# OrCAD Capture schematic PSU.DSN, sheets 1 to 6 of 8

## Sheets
1 Hirose70239: size A; title: Adapter for connecting IR-256x192(FPC-39)  to IR-640x512(Hirose-70); rev: A1
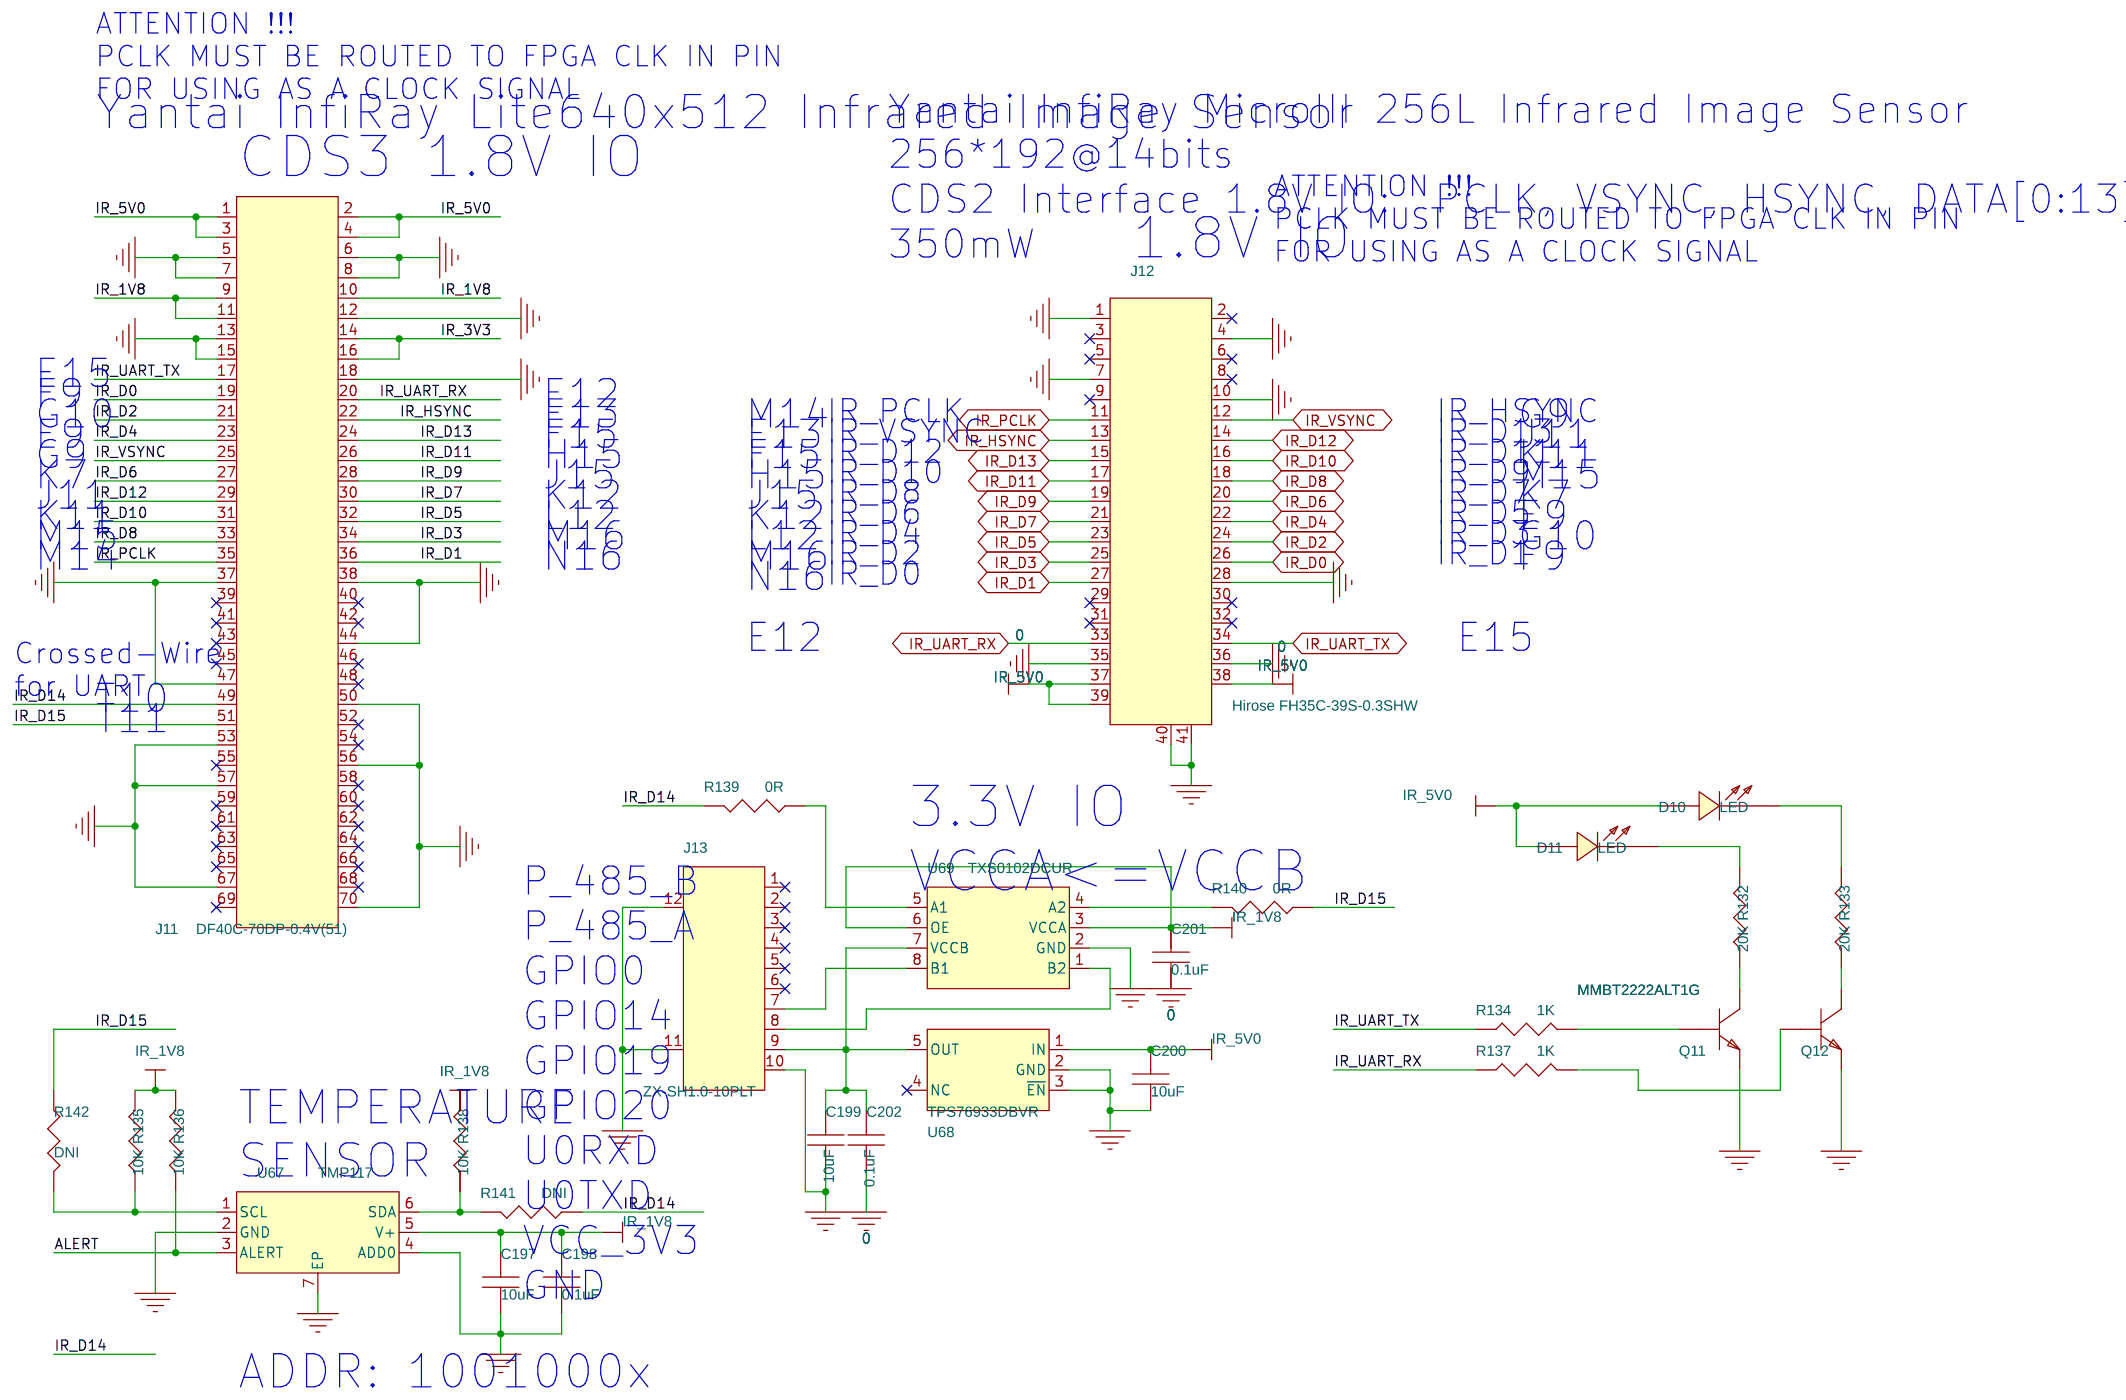
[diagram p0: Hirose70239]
2 ElectricFieldSensor: size A2
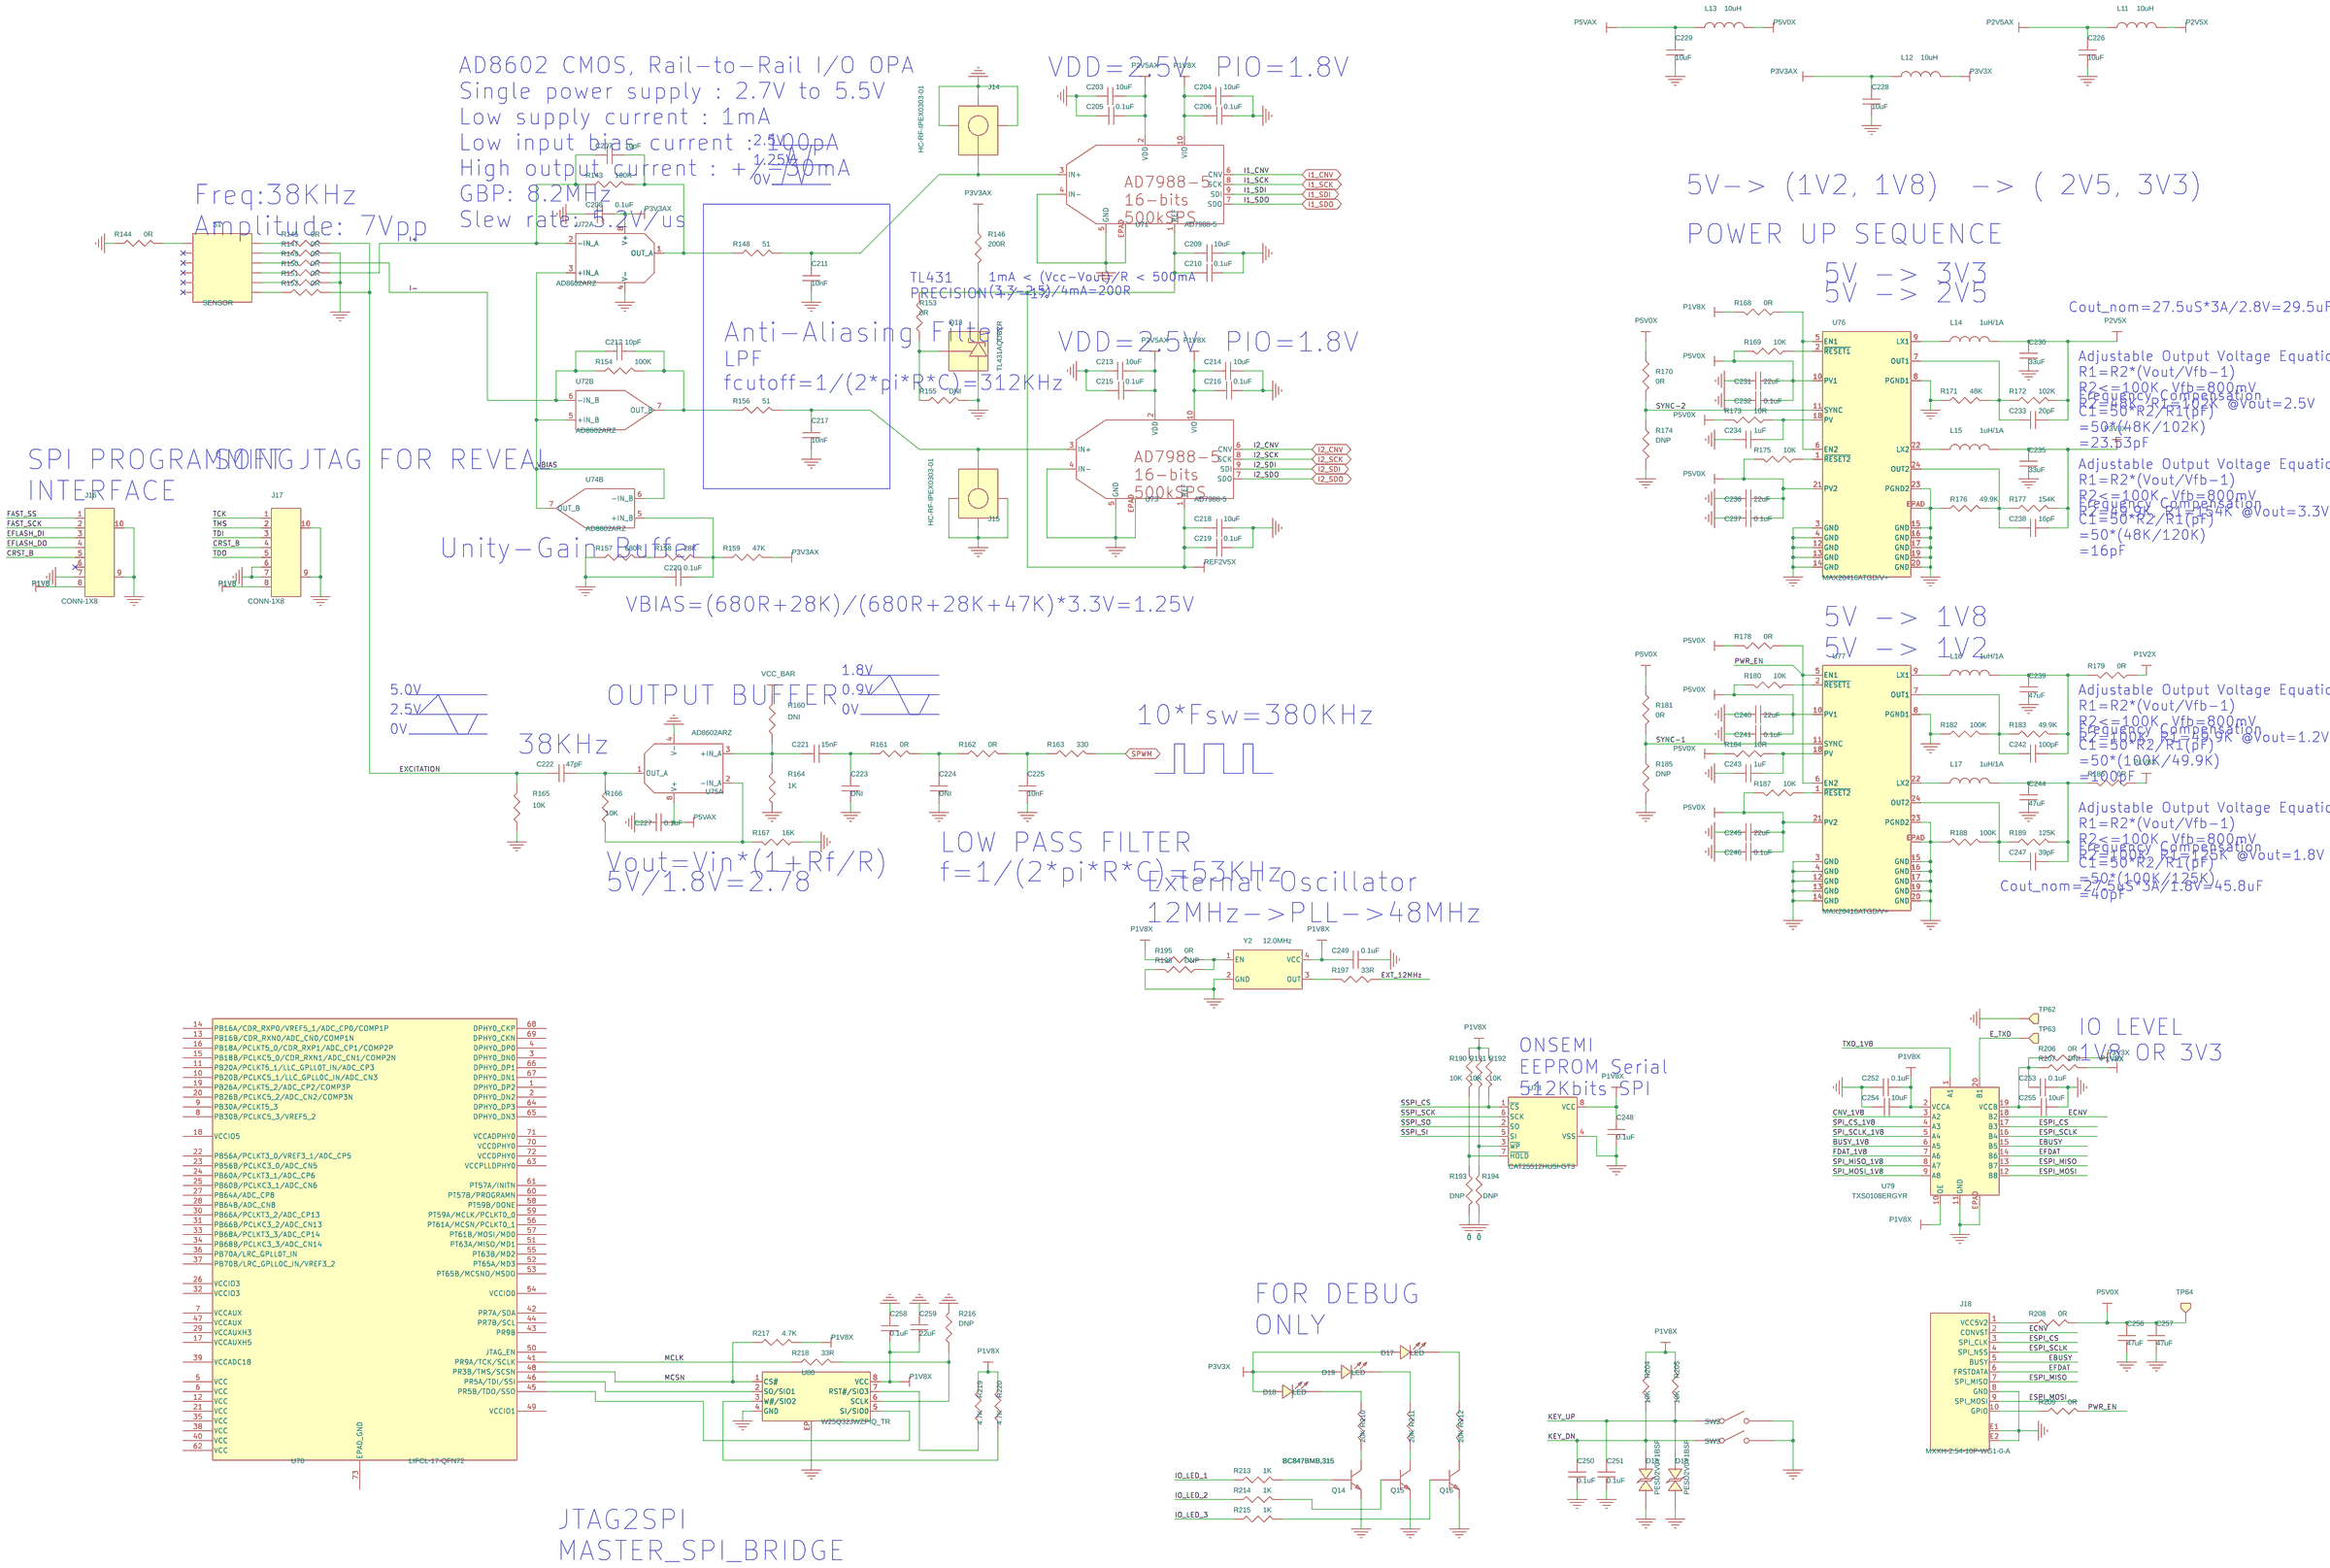
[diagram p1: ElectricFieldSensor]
3 PG_Adapter: size A; title: GENERIC PROGRAMMING ADAPTER FOR LATTICE FPGA
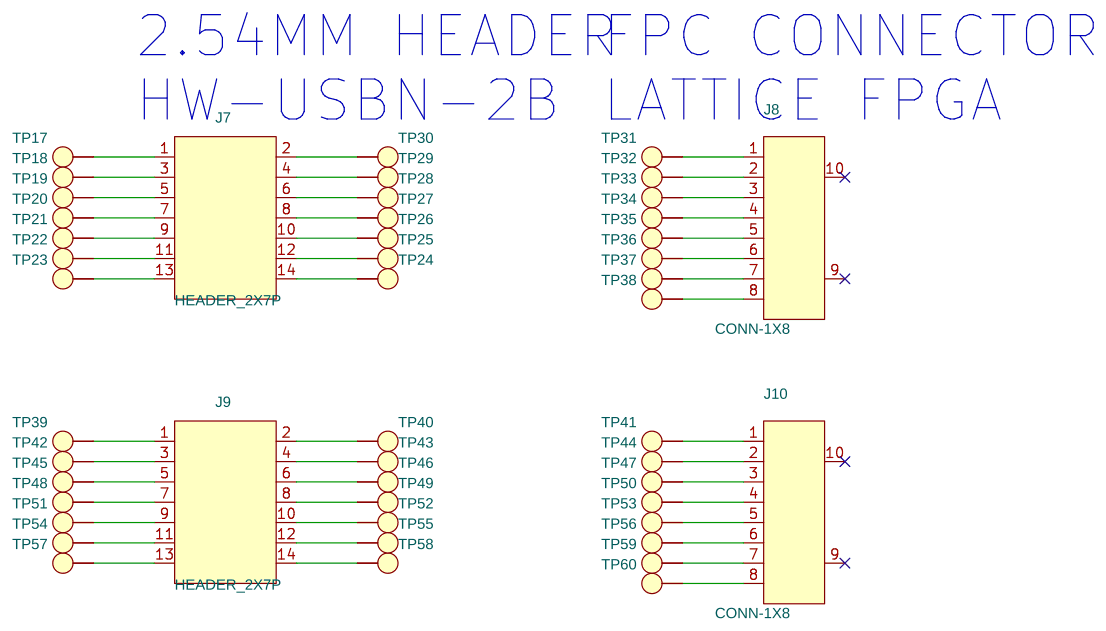
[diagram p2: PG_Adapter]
4 PSU1W: size A3
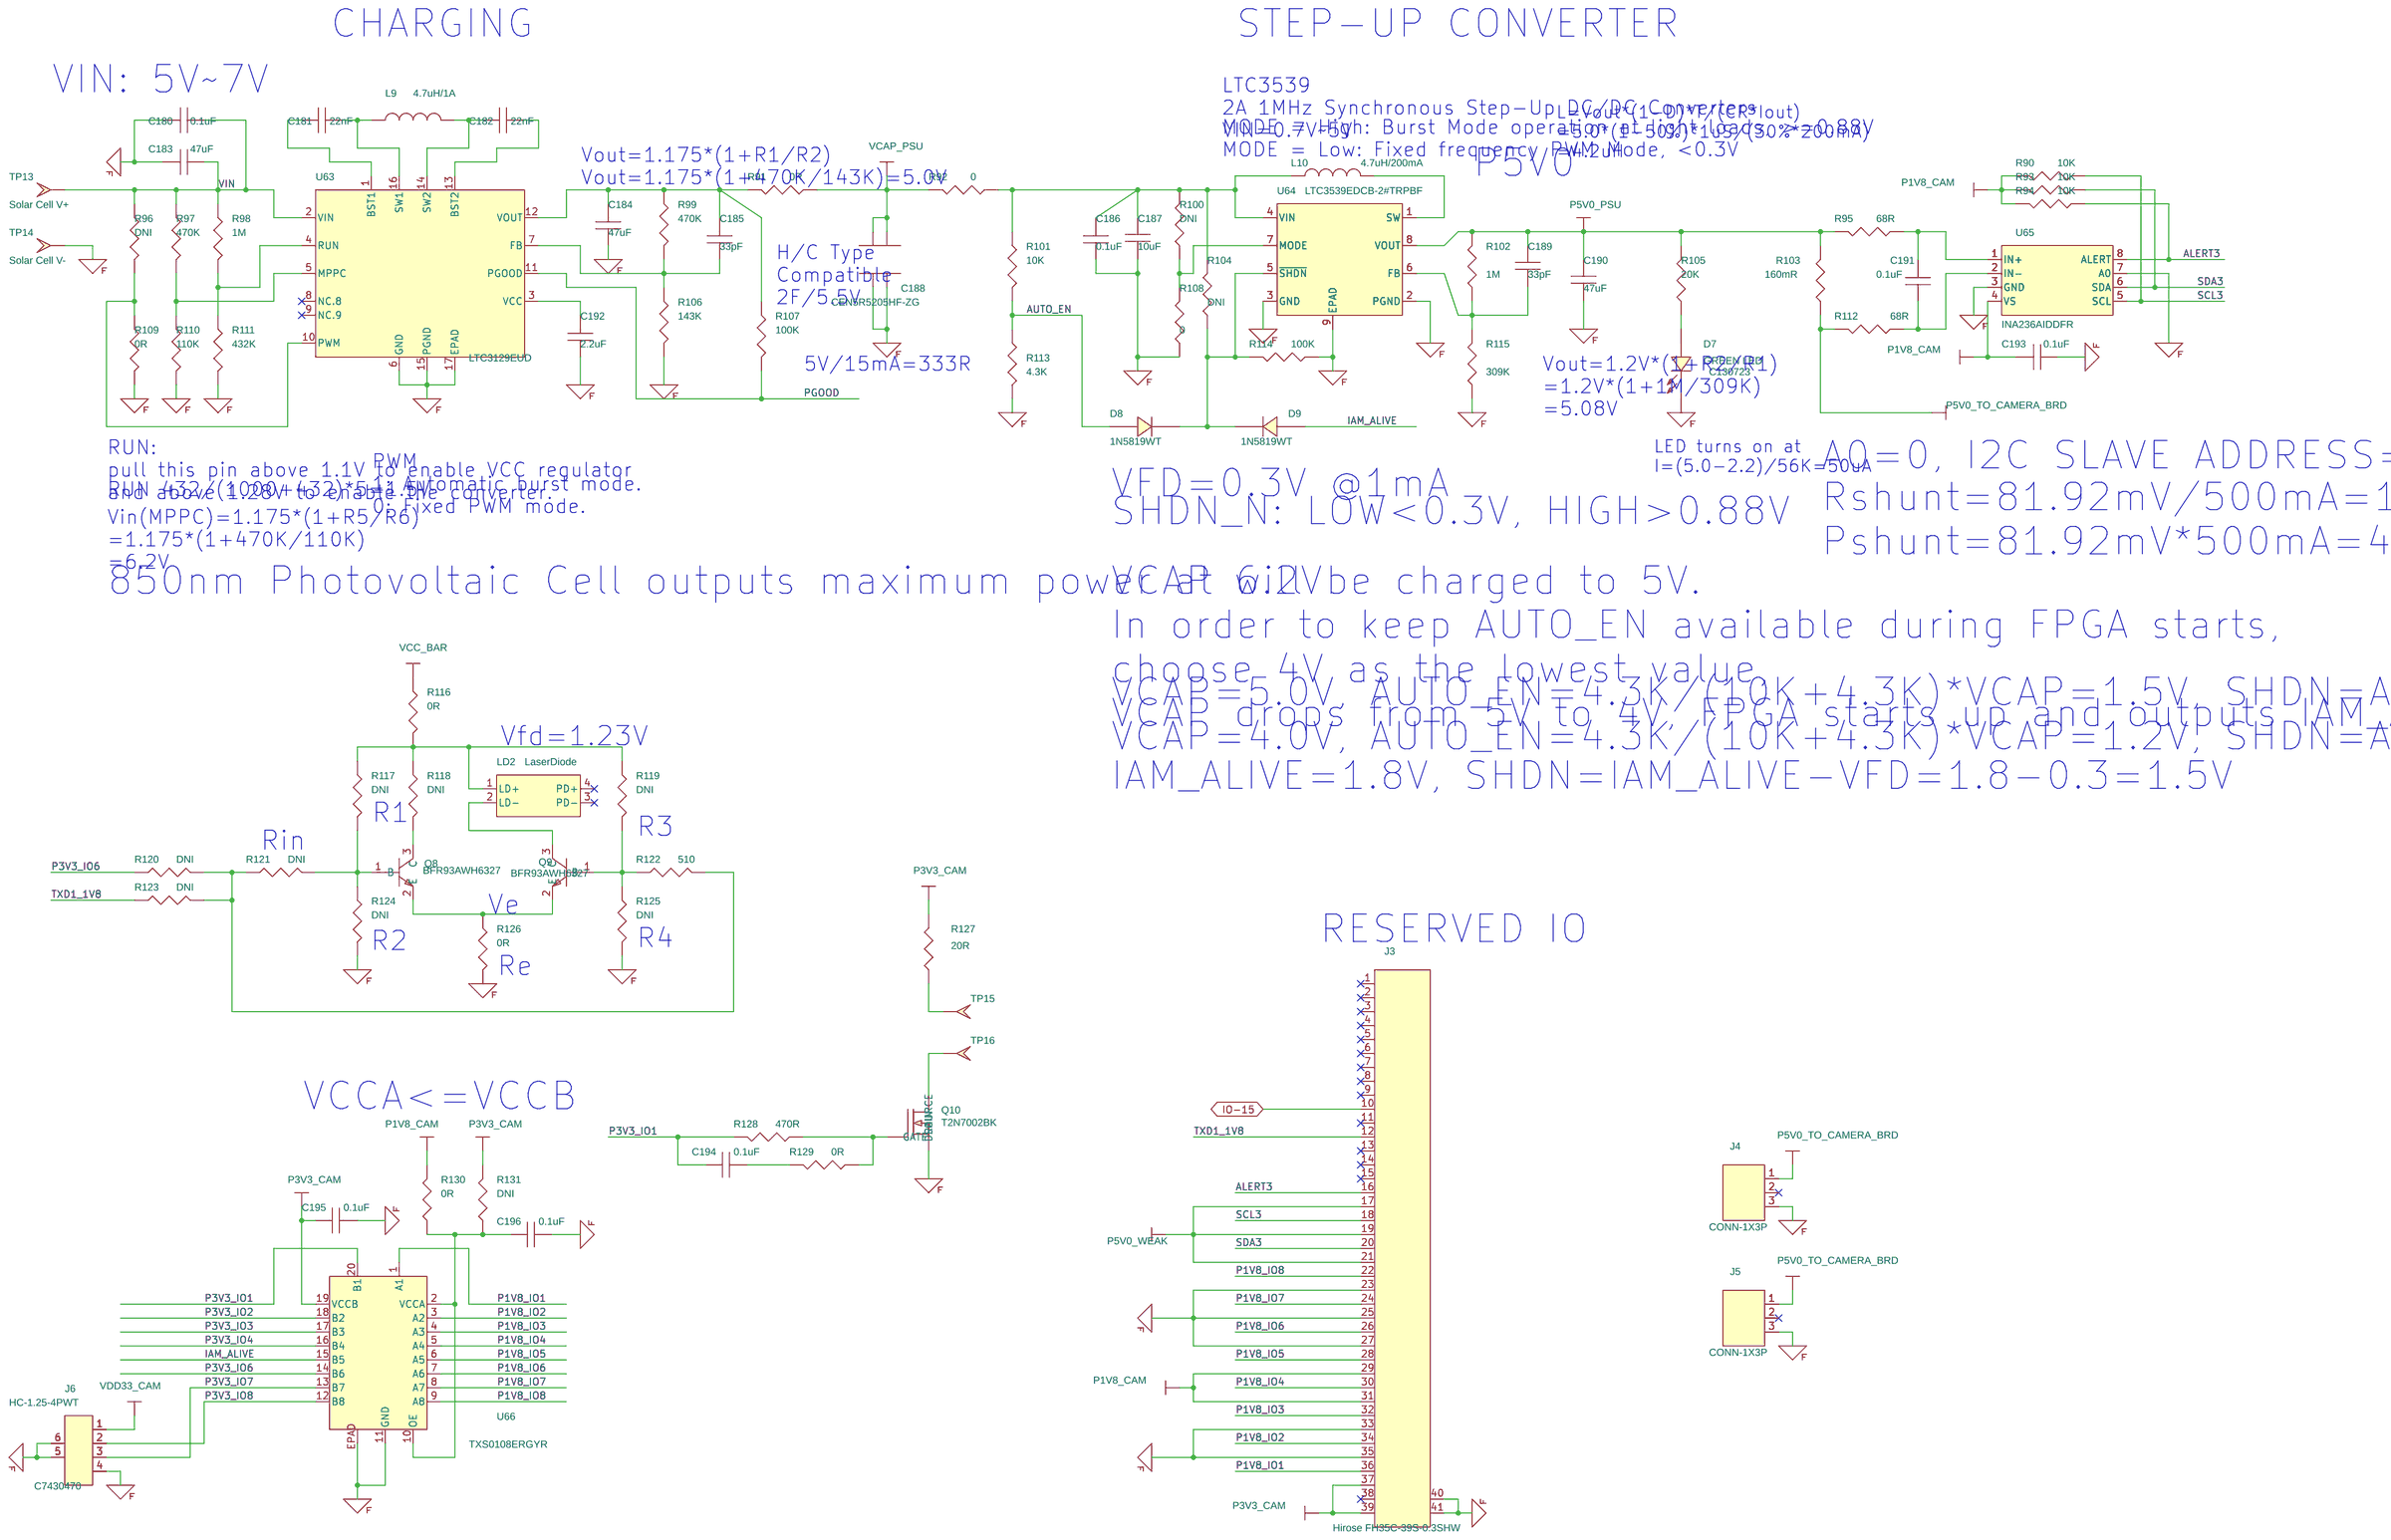
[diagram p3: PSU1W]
5 MAGIC2956: size A4; title: TMR SENSOR (CHINA DOMESTIC IC SUPPLIER); note: TMR PROJECT
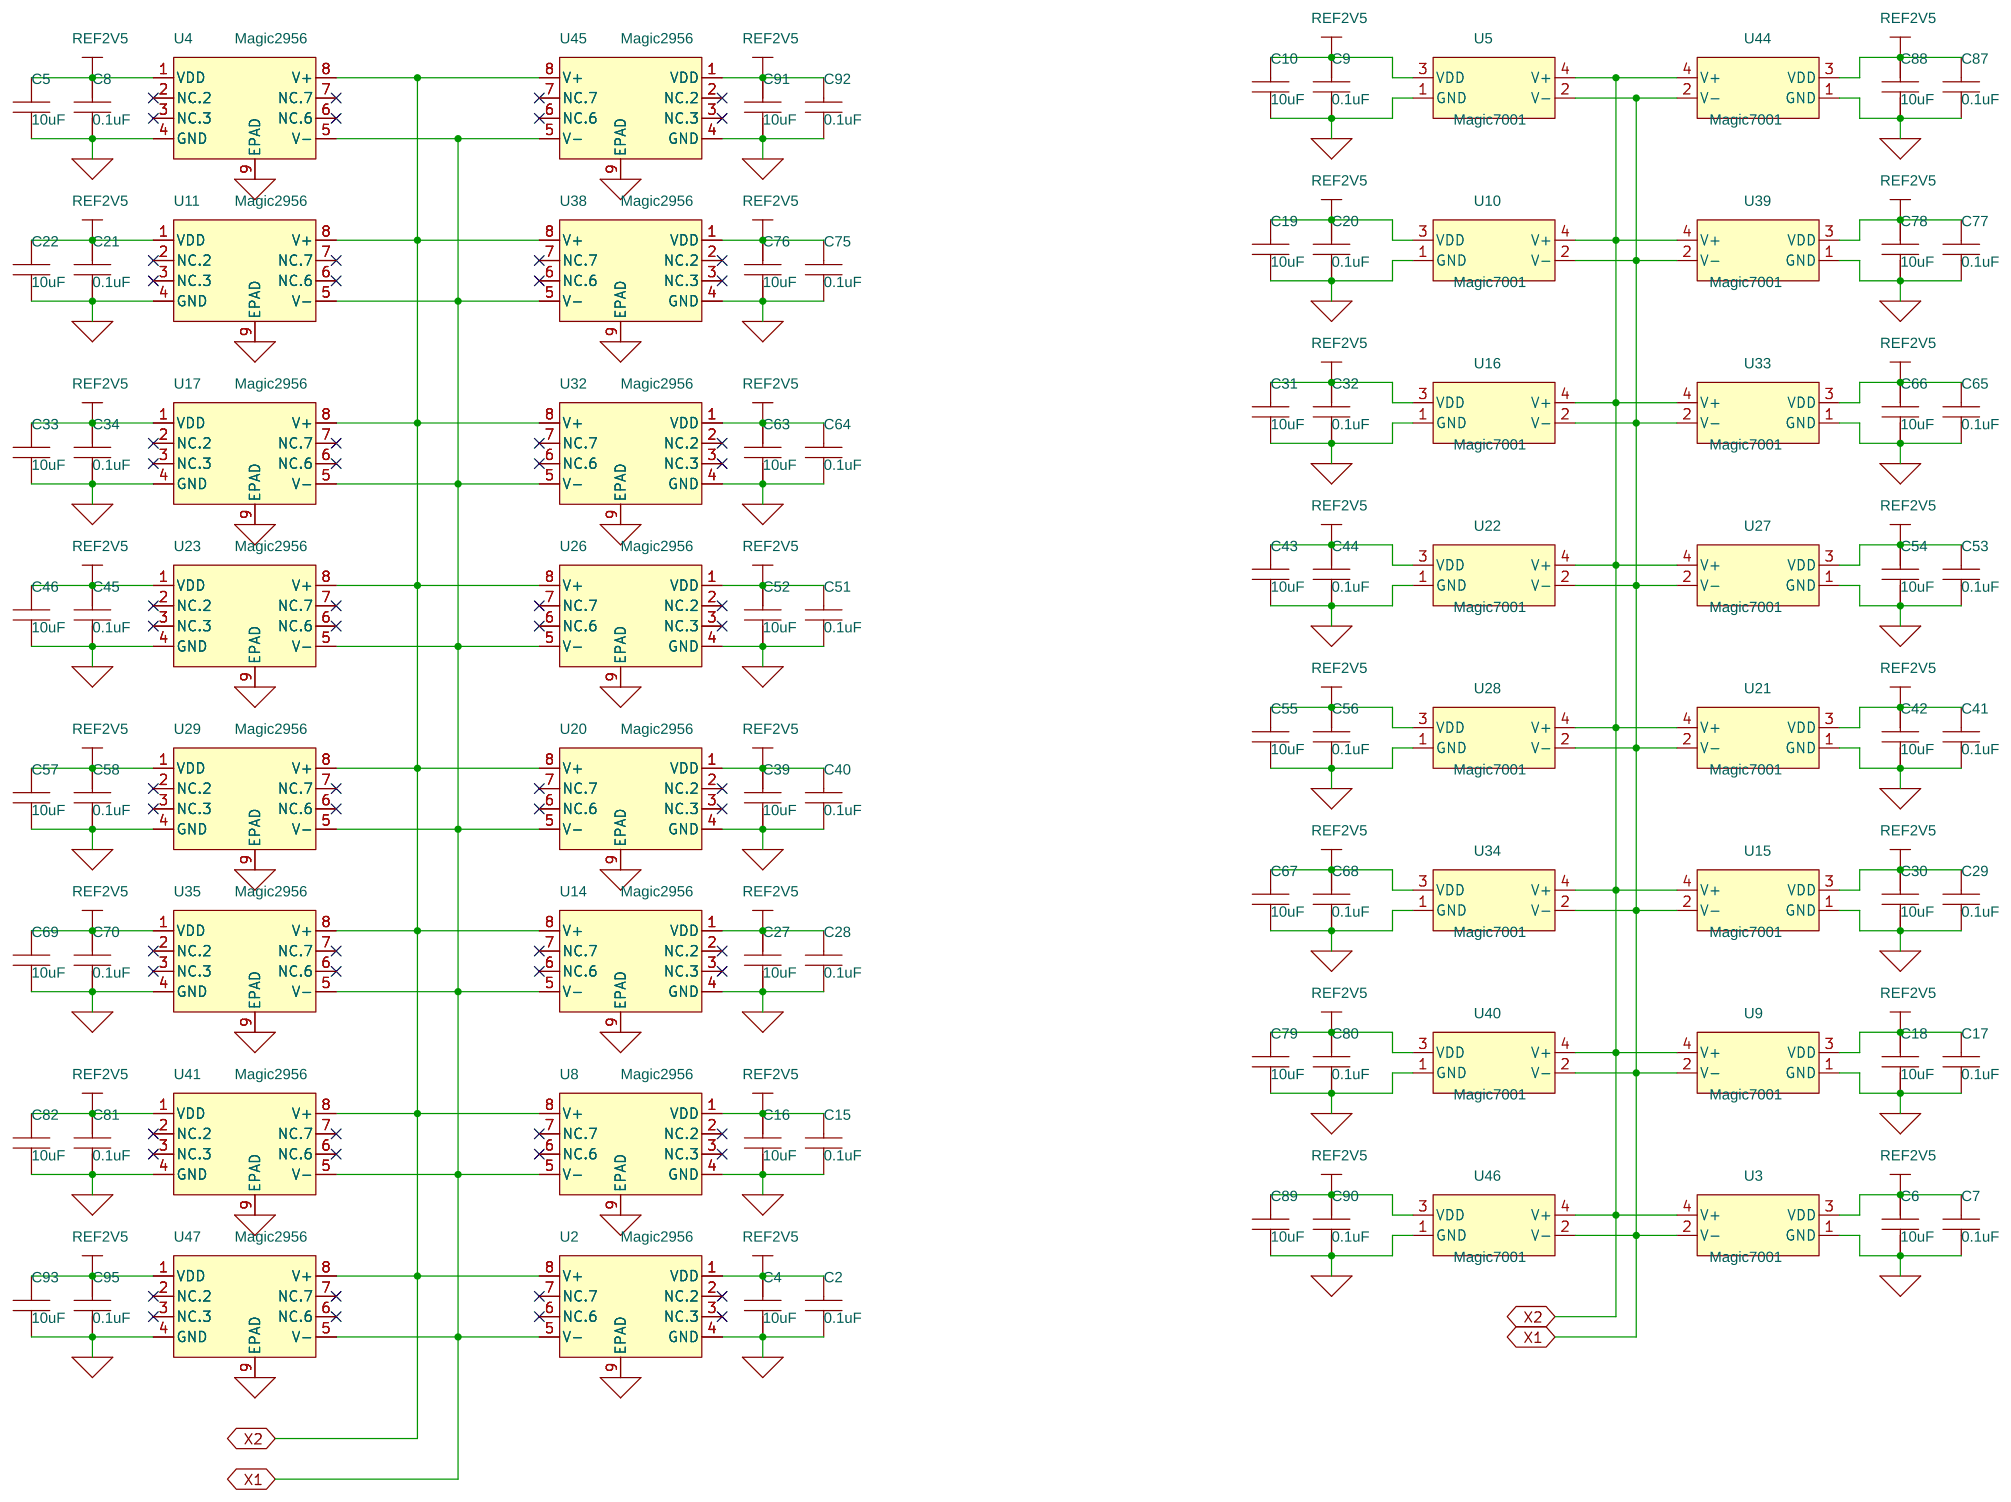
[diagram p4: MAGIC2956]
6 ADC: size A; title: TMR SENSOR ( FOREIGN IC SUPPLIER); note: TMR PROJECT
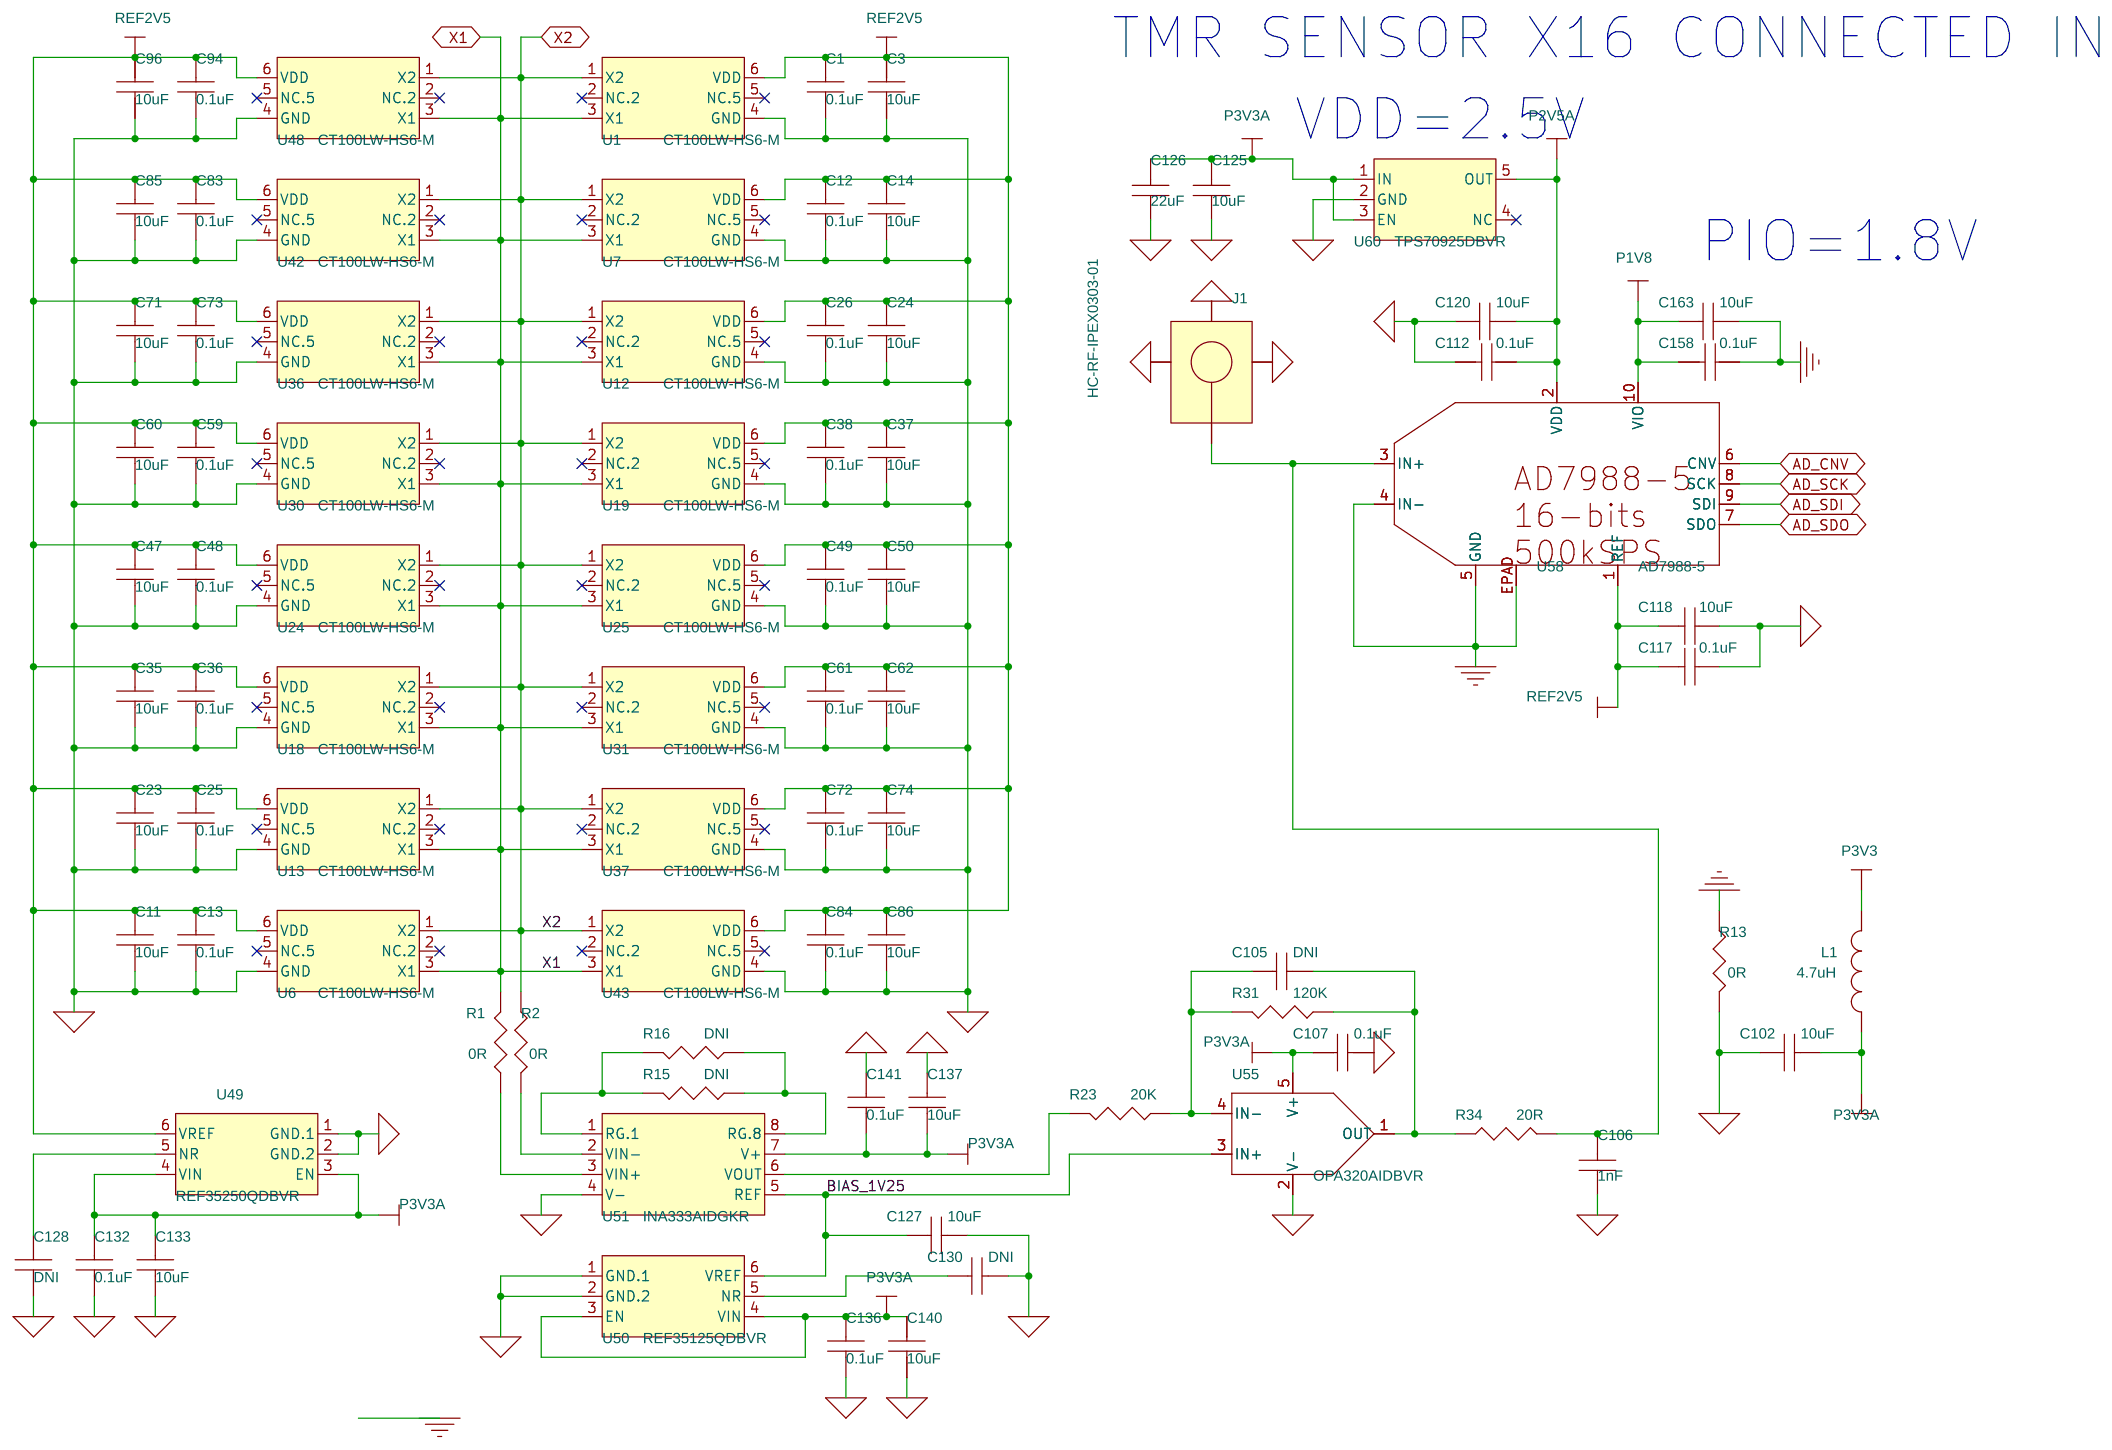
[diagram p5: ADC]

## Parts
sheet ADC
C1  0.1uF  [C0402_SMT]
C3  10uF  [C0402_SMT]
C11  10uF  [C0402_SMT]
C12  0.1uF  [C0402_SMT]
C13  0.1uF  [C0402_SMT]
C14  10uF  [C0402_SMT]
C23  10uF  [C0402_SMT]
C24  10uF  [C0402_SMT]
C25  0.1uF  [C0402_SMT]
C26  0.1uF  [C0402_SMT]
C35  10uF  [C0402_SMT]
C36  0.1uF  [C0402_SMT]
C37  10uF  [C0402_SMT]
C38  0.1uF  [C0402_SMT]
C47  10uF  [C0402_SMT]
C48  0.1uF  [C0402_SMT]
C49  0.1uF  [C0402_SMT]
C50  10uF  [C0402_SMT]
C59  0.1uF  [C0402_SMT]
C60  10uF  [C0402_SMT]
C61  0.1uF  [C0402_SMT]
C62  10uF  [C0402_SMT]
C71  10uF  [C0402_SMT]
C72  0.1uF  [C0402_SMT]
C73  0.1uF  [C0402_SMT]
C74  10uF  [C0402_SMT]
C83  0.1uF  [C0402_SMT]
C84  0.1uF  [C0402_SMT]
C85  10uF  [C0402_SMT]
C86  10uF  [C0402_SMT]
C94  0.1uF  [C0402_SMT]
C96  10uF  [C0402_SMT]
C102  10uF  [C0402_SMT]
C105  DNI  [C0402_SMT]
C106  1nF  [C0402_SMT]
C107  0.1uF  [C0402_SMT]
C112  0.1uF  [C0402_SMT]
C117  0.1uF  [C0402_SMT]
C118  10uF  [C0402_SMT]
C120  10uF  [C0402_SMT]
C125  10uF  [C0402_SMT]
C126  22uF  [C0603_SMT]
C127  10uF  [C0402_SMT]
C128  DNI  [C0402_SMT]
C130  DNI  [C0402_SMT]
C132  0.1uF  [C0402_SMT]
C133  10uF  [C0402_SMT]
C136  0.1uF  [C0402_SMT]
C137  10uF  [C0402_SMT]
C140  10uF  [C0402_SMT]
C141  0.1uF  [C0402_SMT]
C158  0.1uF  [C0402_SMT]
C163  10uF  [C0402_SMT]
J1  HC-RF-IPEX0303-01  [IPEX_SMD_4P]
L1  4.7uH  [L0603_SMT]
R1  0R  [R0402_SMT]
R2  0R  [R0402_SMT]
R13  0R  [R0402_SMT]
R15  DNI  [R0402_SMT]
R16  DNI  [R0402_SMT]
R23  20K  [R0402_SMT]
R31  120K  [R0402_SMT]
R34  20R  [R0402_SMT]
U1  CT100LW-HS6-M  [TSOT-23-6]
U6  CT100LW-HS6-M  [TSOT-23-6]
U7  CT100LW-HS6-M  [TSOT-23-6]
U12  CT100LW-HS6-M  [TSOT-23-6]
U13  CT100LW-HS6-M  [TSOT-23-6]
U18  CT100LW-HS6-M  [TSOT-23-6]
U19  CT100LW-HS6-M  [TSOT-23-6]
U24  CT100LW-HS6-M  [TSOT-23-6]
U25  CT100LW-HS6-M  [TSOT-23-6]
U30  CT100LW-HS6-M  [TSOT-23-6]
U31  CT100LW-HS6-M  [TSOT-23-6]
U36  CT100LW-HS6-M  [TSOT-23-6]
U37  CT100LW-HS6-M  [TSOT-23-6]
U42  CT100LW-HS6-M  [TSOT-23-6]
U43  CT100LW-HS6-M  [TSOT-23-6]
U48  CT100LW-HS6-M  [TSOT-23-6]
U49  REF35250QDBVR  [SOT-23-6]
U50  REF35125QDBVR  [SOT-23-6]
U51  INA333AIDGKR  [MSOP-8]
U55  OPA320AIDBVR  [SOT-23-5]
U58  AD7988-5  [MSOP-10]
U60  TPS70925DBVR  [SOT-23-5]
sheet ElectricFieldSensor
C203  10uF  [C0402_SMT]
C204  10uF  [C0402_SMT]
C205  0.1uF  [C0402_SMT]
C206  0.1uF  [C0402_SMT]
C207  10pF  [C0402_SMT]
C208  0.1uF  [C0402_SMT]
C209  10uF  [C0402_SMT]
C210  0.1uF  [C0402_SMT]
C211  10nF  [C0402_SMT]
C212  10pF  [C0402_SMT]
C213  10uF  [C0402_SMT]
C214  10uF  [C0402_SMT]
C215  0.1uF  [C0402_SMT]
C216  0.1uF  [C0402_SMT]
C217  10nF  [C0402_SMT]
C218  10uF  [C0402_SMT]
C219  0.1uF  [C0402_SMT]
C220  0.1uF  [C0402_SMT]
C221  15nF  [C0402_SMT]
C222  47pF  [C0402_SMT]
C223  DNI  [C0402_SMT]
C224  DNI  [C0402_SMT]
C225  10nF  [C0402_SMT]
C226  10uF  [C0603_SMT]
C227  0.1uF  [C0402_SMT]
C228  10uF  [C0603_SMT]
C229  10uF  [C0603_SMT]
C230  33uF  [C1206_SMT]
C231  22uF  [C0603_SMT]
C232  0.1uF  [C0402_SMT]
C233  20pF  [C0402_SMT]
C234  1uF  [C0402_SMT]
C235  33uF  [C1206_SMT]
C236  22uF  [C0603_SMT]
C237  0.1uF  [C0402_SMT]
C238  16pF  [C0402_SMT]
C239  47uF  [C1206_SMT]
C240  22uF  [C0603_SMT]
C241  0.1uF  [C0402_SMT]
C242  100pF  [C0402_SMT]
C243  1uF  [C0402_SMT]
C244  47uF  [C1206_SMT]
C245  22uF  [C0603_SMT]
C246  0.1uF  [C0402_SMT]
C247  39pF  [C0402_SMT]
C248  0.1uF  [C0402_SMT]
C249  0.1uF  [C0402_SMT]
C250  0.1uF  [C0402_SMT]
C251  0.1uF  [C0402_SMT]
C252  0.1uF  [C0402_SMT]
C253  0.1uF  [C0402_SMT]
C254  10uF  [C0402_SMT]
C255  10uF  [C0402_SMT]
C256  47uF  [C0603_SMT]
C257  47uF  [C0603_SMT]
C258  0.1uF  [C0201_SMT]
C259  22uF  [C0603_SMT]
D15  PESD2V0Y1BSF  [DSN0603-2]
D16  PESD2V0Y1BSF  [DSN0603-2]
D17  LED  [LED0402_SMT]
D18  LED  [LED0402_SMT]
D19  LED  [LED0402_SMT]
J14  HC-RF-IPEX0303-01  [IPEX_SMD_4P]
J15  HC-RF-IPEX0303-01  [IPEX_SMD_4P]
J16  CONN-1X8  [FPC-0D5-8P]
J17  CONN-1X8  [FPC-0D5-8P]
J18  MXXH-2.54-10P-WG1-0-A  [CONN_SMD_1X10P_2D5]
L11  10uH  [L0603_SMT]
L12  10uH  [L0603_SMT]
L13  10uH  [L0603_SMT]
L14  1uH/1A  [IND_SMD_4D4X4D2]
L15  1uH/1A  [IND_SMD_4D4X4D2]
L16  1uH/1A  [IND_SMD_4D4X4D2]
L17  1uH/1A  [IND_SMD_4D4X4D2]
Q13  TL431AQDBZR  [SOT-23-3]
Q14  BC847BMB,315  [DFN-3-1X0D6]
Q15  BC847BMB,315  [DFN-3-1X0D6]
Q16  BC847BMB,315  [DFN-3-1X0D6]
R143  100K  [R0402_SMT]
R144  0R  [R0402_SMT]
R145  0R  [R0402_SMT]
R146  200R  [R0402_SMT]
R147  0R  [R0402_SMT]
R148  51  [R0402_SMT]
R149  0R  [R0402_SMT]
R150  0R  [R0402_SMT]
R151  0R  [R0402_SMT]
R152  0R  [R0402_SMT]
R153  0R  [R0402_SMT]
R154  100K  [R0402_SMT]
R155  DNI  [R0402_SMT]
R156  51  [R0402_SMT]
R157  680R  [R0402_SMT]
R158  28K  [R0402_SMT]
R159  47K  [R0402_SMT]
R160  DNI  [R0402_SMT]
R161  0R  [R0402_SMT]
R162  0R  [R0402_SMT]
R163  330  [R0402_SMT]
R164  1K  [R0402_SMT]
R165  10K  [R0402_SMT]
R166  10K  [R0402_SMT]
R167  16K  [R0402_SMT]
R168  0R  [R0402_SMT]
R169  10K  [R0402_SMT]
R170  0R  [R0402_SMT]
R171  48K  [R0402_SMT]
R172  102K  [R0402_SMT]
R173  10R  [R0402_SMT]
R174  DNP  [R0402_SMT]
R175  10K  [R0402_SMT]
R176  49.9K  [R0402_SMT]
R177  154K  [R0402_SMT]
R178  0R  [R0402_SMT]
R179  0R  [R0402_SMT]
R180  10K  [R0402_SMT]
R181  0R  [R0402_SMT]
R182  100K  [R0402_SMT]
R183  49.9K  [R0402_SMT]
R184  10R  [R0402_SMT]
R185  DNP  [R0402_SMT]
R186  0R  [R0402_SMT]
R187  10K  [R0402_SMT]
R188  100K  [R0402_SMT]
R189  125K  [R0402_SMT]
R190  10K  [R0402_SMT]
R191  10K  [R0402_SMT]
R192  10K  [R0402_SMT]
R193  DNP  [R0402_SMT]
R194  DNP  [R0402_SMT]
R195  0R  [R0402_SMT]
R196  DNP  [R0402_SMT]
R197  33R  [R0402_SMT]
R204  10K  [R0402_SMT]
R205  10K  [R0402_SMT]
R206  0R  [R0402_SMT]
R207  DNI  [R0402_SMT]
R208  0R  [R0603_SMT]
R209  0R  [R0402_SMT]
R210  20K  [R0201_SMT]
R211  20K  [R0201_SMT]
R212  20K  [R0201_SMT]
R213  1K  [R0201_SMT]
R214  1K  [R0201_SMT]
R215  1K  [R0201_SMT]
R216  DNP  [R0201_SMT]
R217  4.7K  [R0201_SMT]
R218  33R  [R0201_SMT]
R219  4.7K  [R0201_SMT]
R220  4.7K  [R0201_SMT]
S1  SENSOR  [EFS-12X10-12P]
SW2  SW KEY-SPST  [SW_SMD_2P_L3D9_W3D0_P4D5]
SW3  SW KEY-SPST  [SW_SMD_2P_L3D9_W3D0_P4D5]
TP62  T POINT F  [TP_THR_CIR_1D0_1D5]
TP63  T POINT F  [TP_THR_CIR_1D0_1D5]
TP64  T POINT F  [TP_THR_CIR_1D0_1D5]
U70  LIFCL-17-QFN72  [QFN-72-EP]
U71  AD7988-5  [MSOP-10]
U72  AD8602ARZ  [SOIC-8]  (sections A,B)
U73  AD7988-5  [MSOP-10]
U74  AD8602ARZ  [SOIC-8]  (section B)
U75  AD8602ARZ  [SOIC-8]  (section A)
U76  MAX20416ATGD/V+  [TQFN-24]
U77  MAX20416ATGD/V+  [TQFN-24]
U78  CAT25512HU5I-GT3  [UDFN-8-2x3]
U79  TXS0108ERGYR  [VQFN-20]
U80  W25Q32JWZPIQ_TR  [WSON-8-EP-6X5MM]
Y2  12.0MHz  [SMD2520-4P]
sheet Hirose70239
C197  10uF  [C0402_SMT]
C198  0.1uF  [C0402_SMT]
C199  10uF  [C0402_SMT]
C200  10uF  [C0402_SMT]
C201  0.1uF  [C0402_SMT]
C202  0.1uF  [C0402_SMT]
D10  LED  [LED0402_SMT]
D11  LED  [LED0402_SMT]
J11  DF40C-70DP-0.4V(51)  [DF40C-70DP-0D4V-51]
J12  Hirose FH35C-39S-0.3SHW  [FH35C-39S-0D3SHW]
J13  ZX-SH1.0-10PLT  [CONN_1X10P_SH1D0]
Q11  MMBT2222ALT1G  [SOT-23-3]
Q12  MMBT2222ALT1G  [SOT-23-3]
R132  20K  [R0402_SMT]
R133  20K  [R0402_SMT]
R134  1K  [R0402_SMT]
R135  10K  [R0402_SMT]
R136  10K  [R0402_SMT]
R137  1K  [R0402_SMT]
R138  10K  [R0402_SMT]
R139  0R  [R0402_SMT]
R140  0R  [R0402_SMT]
R141  DNI  [R0402_SMT]
R142  DNI  [R0402_SMT]
U67  TMP117  [WDFN-6-EP-2x2]
U68  TPS76933DBVR  [SOT-23-5]
U69  TXS0102DCUR  [VSSOP-8]
sheet MAGIC2956
C2  0.1uF  [C0402_SMT]
C4  10uF  [C0402_SMT]
C5  10uF  [C0402_SMT]
C6  10uF  [C0402_SMT]
C7  0.1uF  [C0402_SMT]
C8  0.1uF  [C0402_SMT]
C9  0.1uF  [C0402_SMT]
C10  10uF  [C0402_SMT]
C15  0.1uF  [C0402_SMT]
C16  10uF  [C0402_SMT]
C17  0.1uF  [C0402_SMT]
C18  10uF  [C0402_SMT]
C19  10uF  [C0402_SMT]
C20  0.1uF  [C0402_SMT]
C21  0.1uF  [C0402_SMT]
C22  10uF  [C0402_SMT]
C27  10uF  [C0402_SMT]
C28  0.1uF  [C0402_SMT]
C29  0.1uF  [C0402_SMT]
C30  10uF  [C0402_SMT]
C31  10uF  [C0402_SMT]
C32  0.1uF  [C0402_SMT]
C33  10uF  [C0402_SMT]
C34  0.1uF  [C0402_SMT]
C39  10uF  [C0402_SMT]
C40  0.1uF  [C0402_SMT]
C41  0.1uF  [C0402_SMT]
C42  10uF  [C0402_SMT]
C43  10uF  [C0402_SMT]
C44  0.1uF  [C0402_SMT]
C45  0.1uF  [C0402_SMT]
C46  10uF  [C0402_SMT]
C51  0.1uF  [C0402_SMT]
C52  10uF  [C0402_SMT]
C53  0.1uF  [C0402_SMT]
C54  10uF  [C0402_SMT]
C55  10uF  [C0402_SMT]
C56  0.1uF  [C0402_SMT]
C57  10uF  [C0402_SMT]
C58  0.1uF  [C0402_SMT]
C63  10uF  [C0402_SMT]
C64  0.1uF  [C0402_SMT]
C65  0.1uF  [C0402_SMT]
C66  10uF  [C0402_SMT]
C67  10uF  [C0402_SMT]
C68  0.1uF  [C0402_SMT]
C69  10uF  [C0402_SMT]
C70  0.1uF  [C0402_SMT]
C75  0.1uF  [C0402_SMT]
C76  10uF  [C0402_SMT]
C77  0.1uF  [C0402_SMT]
C78  10uF  [C0402_SMT]
C79  10uF  [C0402_SMT]
C80  0.1uF  [C0402_SMT]
C81  0.1uF  [C0402_SMT]
C82  10uF  [C0402_SMT]
C87  0.1uF  [C0402_SMT]
C88  10uF  [C0402_SMT]
C89  10uF  [C0402_SMT]
C90  0.1uF  [C0402_SMT]
C91  10uF  [C0402_SMT]
C92  0.1uF  [C0402_SMT]
C93  10uF  [C0402_SMT]
C95  0.1uF  [C0402_SMT]
U2  Magic2956  [DFN8L]
U3  Magic7001  [SSIP4L]
U4  Magic2956  [DFN8L]
U5  Magic7001  [SSIP4L]
U8  Magic2956  [DFN8L]
U9  Magic7001  [SSIP4L]
U10  Magic7001  [SSIP4L]
U11  Magic2956  [DFN8L]
U14  Magic2956  [DFN8L]
U15  Magic7001  [SSIP4L]
U16  Magic7001  [SSIP4L]
U17  Magic2956  [DFN8L]
U20  Magic2956  [DFN8L]
U21  Magic7001  [SSIP4L]
U22  Magic7001  [SSIP4L]
U23  Magic2956  [DFN8L]
U26  Magic2956  [DFN8L]
U27  Magic7001  [SSIP4L]
U28  Magic7001  [SSIP4L]
U29  Magic2956  [DFN8L]
U32  Magic2956  [DFN8L]
U33  Magic7001  [SSIP4L]
U34  Magic7001  [SSIP4L]
U35  Magic2956  [DFN8L]
U38  Magic2956  [DFN8L]
U39  Magic7001  [SSIP4L]
U40  Magic7001  [SSIP4L]
U41  Magic2956  [DFN8L]
U44  Magic7001  [SSIP4L]
U45  Magic2956  [DFN8L]
U46  Magic7001  [SSIP4L]
U47  Magic2956  [DFN8L]
sheet PG_Adapter
J7  HEADER_2X7P  [HEADER_2X7P_2D54]
J8  CONN-1X8  [FPC-0D5-8P]
J9  HEADER_2X7P  [HEADER_2X7P_2D54]
J10  CONN-1X8  [FPC-0D5-8P]
TP17  T POINT R  [TP_THR_CIR_2D0_1D2]
TP18  T POINT R  [TP_THR_CIR_2D0_1D2]
TP19  T POINT R  [TP_THR_CIR_2D0_1D2]
TP20  T POINT R  [TP_THR_CIR_2D0_1D2]
TP21  T POINT R  [TP_THR_CIR_2D0_1D2]
TP22  T POINT R  [TP_THR_CIR_2D0_1D2]
TP23  T POINT R  [TP_THR_CIR_2D0_1D2]
TP24  T POINT R  [TP_THR_CIR_2D0_1D2]
TP25  T POINT R  [TP_THR_CIR_2D0_1D2]
TP26  T POINT R  [TP_THR_CIR_2D0_1D2]
TP27  T POINT R  [TP_THR_CIR_2D0_1D2]
TP28  T POINT R  [TP_THR_CIR_2D0_1D2]
TP29  T POINT R  [TP_THR_CIR_2D0_1D2]
TP30  T POINT R  [TP_THR_CIR_2D0_1D2]
TP31  T POINT R  [TP_THR_CIR_2D0_1D2]
TP32  T POINT R  [TP_THR_CIR_2D0_1D2]
TP33  T POINT R  [TP_THR_CIR_2D0_1D2]
TP34  T POINT R  [TP_THR_CIR_2D0_1D2]
TP35  T POINT R  [TP_THR_CIR_2D0_1D2]
TP36  T POINT R  [TP_THR_CIR_2D0_1D2]
TP37  T POINT R  [TP_THR_CIR_2D0_1D2]
TP38  T POINT R  [TP_THR_CIR_2D0_1D2]
TP39  T POINT R  [TP_THR_CIR_2D0_1D2]
TP40  T POINT R  [TP_THR_CIR_2D0_1D2]
TP41  T POINT R  [TP_THR_CIR_2D0_1D2]
TP42  T POINT R  [TP_THR_CIR_2D0_1D2]
TP43  T POINT R  [TP_THR_CIR_2D0_1D2]
TP44  T POINT R  [TP_THR_CIR_2D0_1D2]
TP45  T POINT R  [TP_THR_CIR_2D0_1D2]
TP46  T POINT R  [TP_THR_CIR_2D0_1D2]
TP47  T POINT R  [TP_THR_CIR_2D0_1D2]
TP48  T POINT R  [TP_THR_CIR_2D0_1D2]
TP49  T POINT R  [TP_THR_CIR_2D0_1D2]
TP50  T POINT R  [TP_THR_CIR_2D0_1D2]
TP51  T POINT R  [TP_THR_CIR_2D0_1D2]
TP52  T POINT R  [TP_THR_CIR_2D0_1D2]
TP53  T POINT R  [TP_THR_CIR_2D0_1D2]
TP54  T POINT R  [TP_THR_CIR_2D0_1D2]
TP55  T POINT R  [TP_THR_CIR_2D0_1D2]
TP56  T POINT R  [TP_THR_CIR_2D0_1D2]
TP57  T POINT R  [TP_THR_CIR_2D0_1D2]
TP58  T POINT R  [TP_THR_CIR_2D0_1D2]
TP59  T POINT R  [TP_THR_CIR_2D0_1D2]
TP60  T POINT R  [TP_THR_CIR_2D0_1D2]
sheet PSU1W
C180  0.1uF  [C0402_SMT]
C181  22nF  [C0402_SMT]
C182  22nF  [C0402_SMT]
C183  47uF  [C1206_SMT]
C184  47uF  [C1206_SMT]
C185  33pF  [C0402_SMT]
C186  0.1uF  [C0402_SMT]
C187  10uF  [C0603_SMT]
C188  CEN5R5205HF-ZG  [SUC_C_5D0_21D5_H_20D5]
C189  33pF  [C0402_SMT]
C190  47uF  [C1206]
C191  0.1uF  [C0402_SMT]
C192  2.2uF  [C0402_SMT]
C193  0.1uF  [C0402_SMT]
C194  0.1uF  [C0402_SMT]
C195  0.1uF  [C0402_SMT]
C196  0.1uF  [C0402_SMT]
D7  GREEN LED  [LED0402_SMT]
D8  1N5819WT  [SOD-523]
D9  1N5819WT  [SOD-523]
J3  Hirose FH35C-39S-0.3SHW  [FH35C-39S-0D3SHW_REV]
J4  CONN-1X3P  [CONN-1x3P-2D54]
J5  CONN-1X3P  [CONN-1x3P-2D54]
J6  HC-1.25-4PWT  [SMD-1D25-4P-DEG0]
L9  4.7uH/1A  [IND_SMD_4D4X4D2]
L10  4.7uH/200mA  [IND_SMD_4D4X4D2]
LD2  LaserDiode  [LD_CIR_THR_4P]
Q8  BFR93AWH6327  [SOT23-3]
Q9  BFR93AWH6327  [SOT23-3]
Q10  T2N7002BK  [SOT23-3]
R90  10K  [R0402_SMT]
R91  0R  [R0402_SMT]
R92  0  [R0402_SMT]
R93  10K  [R0402_SMT]
R94  10K  [R0402_SMT]
R95  68R  [R0402_SMT]
R96  DNI  [R0402_SMT]
R97  470K  [R0402_SMT]
R98  1M  [R0402_SMT]
R99  470K  [R0402_SMT]
R100  DNI  [R0402_SMT]
R101  10K  [R0402_SMT]
R102  1M  [R0402_SMT]
R103  160mR  [R0805_SMT]
R104  DNI  [R0402_SMT]
R105  20K  [R0402_SMT]
R106  143K  [R0402_SMT]
R107  100K  [R0402_SMT]
R108  0  [R0402_SMT]
R109  0R  [R0402_SMT]
R110  110K  [R0402_SMT]
R111  432K  [R0402_SMT]
R112  68R  [R0402_SMT]
R113  4.3K  [R0402_SMT]
R114  100K  [R0402_SMT]
R115  309K  [R0402_SMT]
R116  0R  [R0402_SMT]
R117  DNI  [R0402_SMT]
R118  DNI  [R0402_SMT]
R119  DNI  [R0402_SMT]
R120  DNI  [R0402_SMT]
R121  DNI  [R0402_SMT]
R122  510  [R0402_SMT]
R123  DNI  [R0402_SMT]
R124  DNI  [R0402_SMT]
R125  DNI  [R0402_SMT]
R126  0R  [R0402_SMT]
R127  20R  [R0402_SMT]
R128  470R  [R0402_SMT]
R129  0R  [R0402_SMT]
R130  0R  [R0402_SMT]
R131  DNI  [R0402_SMT]
TP13  Solar Cell V+  [TP_THR_1D8_1D2]
TP14  Solar Cell V-  [TP_THR_1D8_1D2]
TP15  T POINT A  [TP_THR_CIR_0D8_1D2]
TP16  T POINT A  [TP_THR_CIR_0D8_1D2]
U63  LTC3129EUD  [QFN-16-3x3]
U64  LTC3539EDCB-2#TRPBF  [DFN-8]
U65  INA236AIDDFR  [TSOT-23-8]
U66  TXS0108ERGYR  [VQFN-20]

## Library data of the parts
C1 C2 C7-C9 C12 C13 C15 C17 C20 C21 C25 C26 C28 C29 C32 C34 C36 C38 C40 C41 C44 C45 C48 C49 C51 C53 C56 C58 C59 C61 C64 C65 C68 C70 C72 C73 C75 C77 C80 C81 C83 C84 C87 C90 C92 C94 C95 C105-C107 C128 C130 C136 C141 = CAP_NP: JLC: C14445
C3-C6 C10 C11 C14 C16 C18 C19 C22-C24 C27 C30 C31 C33 C35 C37 C39 C42 C43 C46 C47 C50 C52 C54 C55 C57 C60 C62 C63 C66 C67 C69 C71 C74 C76 C78 C79 C82 C85 C86 C88 C89 C91 C93 C96 C102 C127 C132 C133 C137 C140 = CAP_NP: JLC: C15195
C112 C120 C125 C158 C163 C194-C208 C211-C217 C220-C229 = CAP_NP
C117 C118 C209 C210 C218 C219 = CAP_NP: SCLZSC: 10V
C126 C181 C182 C185 C187 C192 C231 C232 C234 C236 C237 C240 C241 C243 C245 C246 C256 C257 = CAP_NP: Memo: MLCC 10V - Kyocera AVXF951A106MPAAQ2; SIGNAL_MODEL: DEFAULT_CAPACITOR_1e+07pF_2_1
J1 J14 J15 = IPEX
L1 L11-L13 = INDUCTOR
R1 R2 R13 R15 R16 R23 R31 R34 = R: JLC: C60490
U1 U6 U7 U12 U13 U18 U19 U24 U25 U30 U31 U36 U37 U42 U43 U48 = CT100LW-HS6-M
U49 = REF35250QDBVR
U50 = REF35125QDBVR
U51 = INA333AIDGKR
U55 = OPA320AIDBVR
U58 U71 U73 = AD7988-5: SCLZSC: AD7988-5BRMZ-RL7
U60 = TPS70925DBVR
C183 C184 C230 C235 C239 C244 = CAP_NP: Memo: TDK MLCC 10V CGA5L1X7S1A226MT0Y0N; SIGNAL_MODEL: DEFAULT_CAPACITOR_2.2e+07pF_2_1
C233 C238 C242 C247-C249 C252-C255 C258 = CAP_NP: JLC: C307331; Memo: MLCC 10V - Kyocera AVXF951A106MPAAQ2; SIGNAL_MODEL: DEFAULT_CAPACITOR_1e+07pF_2_1
C250 C251 = CAP_NP: JLC: C307331
C190 C259 = CAP_NP: JLC: C12891; Memo: TDK MLCC 10V CGA5L1X7S1A226MT0Y0N; SIGNAL_MODEL: DEFAULT_CAPACITOR_2.2e+07pF_2_1
D15 D16 = DIODE_TVS_BI-DIR
D7 D10 D11 D17-D19 = LED: JLC: C130723
J8 J10 J16 J17 = CONN-1X8
J18 = CONN-1X10P
L9 L10 L14-L17 = INDUCTOR: JLC: C167208; Memo: 4.7uH 1A - TDK VLS3015ET-4R7M 3.0mm(L)*3.0mm(W)*1.5mm(H); SIGNAL_MODEL: DEFAULT_INDUCTOR_4700nH_2_1
Q13 = TL431AQDBZR
Q11 Q12 Q14-Q16 = MMBT2222AL: JLC: C82460
R90 R92-R95 R103 R105 R112 R130 R131 R143-R167 = R
R91 R96-R99 R106 R107 R109-R111 R134 R137 R168-R197 R204-R209 R213-R220 = R: JLC: C106231; SIGNAL_MODEL: DEFAULT_RESISTOR_10000OHM_2_1
R132 R133 R135 R136 R138-R142 R210-R212 = R: JLC: C2930116
S1 = SENSOR
SW2 SW3 = SW_KEY-SPST: JLC: C720477
TP62-TP64 = T_POINT_F
U70 = LIFCL-17-QFN72
U72 U74 U75 = AD8616ARZ
U76 U77 = MAX20416ATGD_V+
U78 = CAT25512HU5I-GT3
U79 = TXS0108ERGYR: JLC: C90706
U80 = GD25Q128ESIGR
Y2 = OSCILLATOR
J11 = Header2x35: Memo: SMD 2 ROWS 70 COLUMNS Connector
J12 = FPC_39
J13 = Connector_1x10P
U67 = TMP117
U68 = TPS76933DBVR
U69 = TXS0102DCUR
U2 U4 U8 U11 U14 U17 U20 U23 U26 U29 U32 U35 U38 U41 U45 U47 = Magic2956
U3 U5 U9 U10 U15 U16 U21 U22 U27 U28 U33 U34 U39 U40 U44 U46 = Magic7001
J7 J9 = HEADER_2X7P
TP17-TP60 = T_POINT_R
C180 C186 = CAP_NP: Memo: SMD CAPACITOR 10V
C188 = SuperCapacitor
C189 C191 C193 = CAP_NP: JLC: C327064; SIGNAL_MODEL: DEFAULT_CAPACITOR_33.000000pF_2_1
D8 D9 = DIODE: JLC: C83482
J3 = FH35C-39S-0DSHW
J4 J5 = CONN-1X3P
J6 = SIP-1x4: JLC: C7430470
LD2 = LaserDiode_0: Memo: Laser Diode
Q8 Q9 = 2SC1815: JLC: C727146; Memo: NPN TRANSISTOR
Q10 = MOSFET_N_0
R100 R101 R104 R108 R113 R114 = R: SIGNAL_MODEL: DEFAULT_RESISTOR_10000OHM_2_1
R102 = R: JLC: C144787; SIGNAL_MODEL: DEFAULT_RESISTOR_0.001OHM_2_1
R115 = R: JLC: C171694; SIGNAL_MODEL: DEFAULT_RESISTOR_562000OHM_2_1
R116 R118 R126-R129 = R: SIGNAL_MODEL: DEFAULT_RESISTOR_40.000000OHM_2_1
R117 R119-R125 = R: SIGNAL_MODEL: DEFAULT_RESISTOR_510.000000OHM_2_1
TP13 TP14 = T_POINT_A: Memo: SMD Test Point Outer Diameter 2.0mm
TP15 TP16 = T_POINT_A
U63 = LTC3129EUD
U64 = LTC3539EDCB#PBF: JLC: C462652; Memo: 2A, 1MHz/2MHz Synchronous Step-Up DC/DC Converters
U65 = INA236AIDDFR
U66 = TXS0108ERGYR

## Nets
GND: C158.1 C163.2 J16.7 J16.9 J16.10 J17.6 J17.7 J17.9 J17.10 R13.1 R196.2 U58.4(IN-) U58.5(GND) U58.EPAD U80.EP Y2.2(GND) ; also on sheet 7
GND_FIELD SIGNAL: C180.2 C183.2 C184.1 C186.1 C187.2 C188.2 C188.4 C190.2 C192.1 C193.1 C195.2 C196.2 D7.1(CATHODE) J3.23 J3.25 J3.27 J3.33 J3.35 J3.40 J3.41 J4.3 J5.3 J6.4 J6.5 J6.6 Q10.2(SOURCE) R106.2 R108.1 R109.2 R110.2 R111.2 R113.2 R114.1 R115.1 R124.2 R125.2 R126.2 TP14.1(TP) U63.6(GND) U63.15(PGND) U63.17(EPAD) U64.2(PGND) U64.3(GND) U64.9(EPAD) U65.3(GND) U65.7(A0) U66.11(GND) U66.EPAD
GND_SIGNAL: C1.2 C2.2 C3.2 C4.2 C5.2 C6.2 C7.2 C8.2 C9.2 C10.2 C11.2 C12.2 C13.2 C14.2 C15.2 C16.2 C17.2 C18.2 C19.2 C20.2 C21.2 C22.2 C23.2 C24.2 C25.2 C26.2 C27.2 C28.2 C29.2 C30.2 C31.2 C32.2 C33.2 C34.2 C35.2 C36.2 C37.2 C38.2 C39.2 C40.2 C41.2 C42.2 C43.2 C44.2 C45.2 C46.2 C47.2 C48.2 C49.2 C50.2 C51.2 C52.2 C53.2 C54.2 C55.2 C56.2 C57.2 C58.2 C59.2 C60.2 C61.2 C62.2 C63.2 C64.2 C65.2 C66.2 C67.2 C68.2 C69.2 C70.2 C71.2 C72.2 C73.2 C74.2 C75.2 C76.2 C77.2 C78.2 C79.2 C80.2 C81.2 C82.2 C83.2 C84.2 C85.2 C86.2 C87.2 C88.2 C89.2 C90.2 C91.2 C92.2 C93.2 C94.2 C95.2 C96.2 C102.1 C106.1 C107.2 C112.2 C117.1 C118.1 C120.1 C125.1 C126.1 C127.2 C128.2 C130.2 C132.2 C133.2 C136.2 C137.1 C140.2 C141.1 J1.2 J1.3 J1.4 R13.2 U1.4(GND) U2.4(GND) U2.9(EPAD) U3.1(GND) U4.4(GND) U4.9(EPAD) U5.1(GND) U6.4(GND) U7.4(GND) U8.4(GND) U8.9(EPAD) U9.1(GND) U10.1(GND) U11.4(GND) U11.9(EPAD) U12.4(GND) U13.4(GND) U14.4(GND) U14.9(EPAD) U15.1(GND) U16.1(GND) U17.4(GND) U17.9(EPAD) U18.4(GND) U19.4(GND) U20.4(GND) U20.9(EPAD) U21.1(GND) U22.1(GND) U23.4(GND) U23.9(EPAD) U24.4(GND) U25.4(GND) U26.4(GND) U26.9(EPAD) U27.1(GND) U28.1(GND) U29.4(GND) U29.9(EPAD) U30.4(GND) U31.4(GND) U32.4(GND) U32.9(EPAD) U33.1(GND) U34.1(GND) U35.4(GND) U35.9(EPAD) U36.4(GND) U37.4(GND) U38.4(GND) U38.9(EPAD) U39.1(GND) U40.1(GND) U41.4(GND) U41.9(EPAD) U42.4(GND) U43.4(GND) U44.1(GND) U45.4(GND) U45.9(EPAD) U46.1(GND) U47.4(GND) U47.9(EPAD) U48.4(GND) U49.1(GND.1) U49.2(GND.2) U50.1(GND.1) U50.2(GND.2) U51.4(V-) U55.2(V-) U60.2(GND)
P1V2X: R179.1
P1V8: C158.2 C163.1 J16.8 J17.8 U58.10(VIO) ; also on sheet 7
P1V8_CAM: C193.2 J3.29 J3.31 R90.2 R93.2 R94.2 R130.2 U65.4(VS)
P1V8_IO1: J3.36 U66.1(A1)
P1V8_IO2: J3.34 U66.3(A2)
P1V8_IO3: J3.32 U66.4(A3)
P1V8_IO4: J3.30 U66.5(A4)
P1V8_IO5: J3.28 U66.6(A5)
P1V8_IO6: J3.26 U66.7(A6)
P1V8_IO7: J3.24 U66.8(A7)
P1V8_IO8: J3.22 U66.9(A8)
P1V8X: C204.1 C206.2 C214.1 C216.2 C248.2 C249.1 C252.2 C254.1 C258.1 C259.2 R168.2 R186.1 R190.1 R191.1 R192.1 R195.2 R204.1 R205.1 R207.2 R217.2 R219.2 R220.2 U71.10(VIO) U73.10(VIO) U78.8(VCC) U79.2(VCCA) U79.10(OE) U80.8(VCC) Y2.4(VCC)
P2V5A: C112.1 C120.2 U58.2(VDD) U60.5(OUT)
P2V5AX: C203.2 C205.1 C213.2 C215.1 C226.2 L11.1 U71.2(VDD) U73.2(VDD)
P2V5X: C230.1 C233.2 L11.2 L14.2 R172.2
P3V3: L1.1 ; also on sheet 7
P3V3_CAM: C195.1 J3.37 J3.39 R127.2 R131.2 U66.19(VCCB)
P3V3_IO1: C194.1 R128.2 U66.20(B1)
P3V3_IO2: U66.18(B2)
P3V3_IO3: U66.17(B3)
P3V3_IO4: U66.16(B4)
P3V3_IO6: R120.1 U66.14(B6)
P3V3_IO7: J6.3 U66.13(B7)
P3V3_IO8: J6.2 U66.12(B8)
P3V3A: C102.2 C107.1 C125.2 C126.2 C132.1 C133.1 C136.1 C137.2 C140.1 C141.2 L1.2 U49.3(EN) U49.4(VIN) U50.3(EN) U50.4(VIN) U51.7(V+) U55.5(V+) U60.1(IN) U60.3(EN)
P3V3AX: C208.2 C228.2 L12.1 R146.1 R159.2 U72.8(V+)
P3V3X: C235.1 C238.2 D17.2(ANODE) D18.2(ANODE) D19.2(ANODE) L12.2 L15.2 R177.2 R206.2
P5V0_PSU: C189.1 C190.1 R95.2 R102.2 R103.1 R105.2 U64.8(VOUT)
P5V0_TO_CAMERA_BRD: J4.1 J5.1 R103.2 R112.2 R116.1
P5V0_WEAK: J3.17 J3.19 J3.21
P5V0X: C231.2 C232.2 C236.2 C237.2 C240.2 C241.2 C245.2 C246.2 C256.2 C257.2 L13.2 R169.2 R170.1 R173.2 R175.2 R178.2 R180.2 R181.1 R184.2 R187.2 R208.2 TP64.1(TP) U76.10(PV1) U76.21(PV2) U77.10(PV1) U77.21(PV2)
P5VAX: C227.2 C229.2 L13.1 R160.2 U75.8(V+)
VCC: U70.5(VCC) U70.6(VCC) U70.12(VCC) U70.21(VCC) U70.35(VCC) U70.38(VCC) U70.40(VCC) U70.62(VCC)
VCCADC18: U70.39(VCCADC18)
VCCADPHY0: U70.71(VCCADPHY0)
VCCAUX: U70.7(VCCAUX) U70.47(VCCAUX)
VCCAUXH3: U70.29(VCCAUXH3)
VCCAUXH5: U70.17(VCCAUXH5)
VCCDPHY0: U70.70(VCCDPHY0) U70.72(VCCDPHY0)
VCCIO0: U70.54(VCCIO0)
VCCIO1: U70.49(VCCIO1)
VCCIO3: U70.26(VCCIO3) U70.32(VCCIO3)
VCCIO5: U70.18(VCCIO5)
VCCPLLDPHY0: U70.63(VCCPLLDPHY0)
VDD33_CAM: J6.1
VIN (page PSU1W): C180.1 C183.1 R96.1 R97.1 R98.1 TP13.1(TP) U63.2(VIN)
0: C197.2 C198.2 C199.2 C200.2 C201.2 C202.2 C203.1 C204.2 C205.2 C206.1 C208.1 C209.1 C210.1 C211.1 C213.1 C214.2 C215.2 C216.1 C217.1 C218.1 C219.1 C220.1 C223.1 C224.1 C225.1 C226.1 C227.1 C228.1 C229.1 C230.2 C231.1 C232.1 C234.1 C235.2 C236.1 C237.1 C239.2 C240.1 C241.1 C243.1 C244.2 C245.1 C246.1 C248.1 C249.2 C250.2 C251.2 C252.1 C253.2 C254.2 C255.1 C256.1 C257.1 C258.2 C259.1 D15.1 D16.1 J11.5 J11.6 J11.7 J11.8 J11.12 J11.13 J11.15 J11.18 J11.37 J11.38 J11.44 J11.47 J11.50 J11.53 J11.56 J11.57 J11.67 J11.70 J12.1 J12.4 J12.7 J12.10 J12.28 J12.35 J12.36 J12.40 J12.41 J13.10 J13.11 J13.12 J14.2 J14.3 J14.4 J15.2 J15.3 J15.4 J18.8(GND) J18.E1 J18.E2 Q11.2(EMITTER) Q12.2(EMITTER) Q13.3 Q14.2(EMITTER) Q15.2(EMITTER) Q16.2(EMITTER) R144.1 R147.2 R151.2 R155.2 R157.1 R164.1 R165.1 R167.1 R171.1 R174.2 R176.1 R182.1 R185.2 R188.1 R193.2 R194.2 R216.2 SW2.2 SW3.2 TP62.1(TP) U67.2(GND) U67.4(ADD0) U67.7(EP) U68.2(GND) U68.3(~{EN}) U69.2(GND) U71.4(IN-) U71.5(GND) U71.EPAD U72.4(V-) U73.4(IN-) U73.5(GND) U73.EPAD U75.4(V-) U76.3(GND) U76.4(GND) U76.8(PGND1) U76.12(GND) U76.13(GND) U76.14(GND) U76.15(GND) U76.16(GND) U76.17(GND) U76.19(GND) U76.20(GND) U76.23(PGND2) U76.EPAD U77.3(GND) U77.4(GND) U77.8(PGND1) U77.12(GND) U77.13(GND) U77.14(GND) U77.15(GND) U77.16(GND) U77.17(GND) U77.19(GND) U77.20(GND) U77.23(PGND2) U77.EPAD U78.4(VSS) U79.11(GND) U79.EPAD U80.4(GND)
AD_CNV: U58.6(CNV) ; also on sheet 7
AD_SCK: U58.8(SCK) ; also on sheet 7
AD_SDI: U58.9(SDI) ; also on sheet 7
AD_SDO: U58.7(SDO) ; also on sheet 7
ALERT3: J3.16 R94.1 U65.8(ALERT)
ALERT (page Hirose70239): R136.1 U67.3(ALERT)
AUTO_EN: D8.2(A) R101.2 R113.1
BIAS_1V25: C127.1 U50.6(VREF) U51.5(REF) U55.3(IN+)
BUSY_1V8: U79.6(A5)
CNV_1V8: U79.3(A2)
CRST_B: J16.5 J17.4
E_TXD: TP63.1(TP) U79.20(B1)
EBUSY: J18.5(BUSY) U79.15(B5)
ECNV: J18.2(CONVST) U79.18(B2)
EFDAT: J18.6(FRSTDATA) U79.14(B6)
EFLASH_DI: J16.3
EFLASH_DO: J16.4
EPAD_GND: U70.73(EPAD_GND)
ESPI_CS: J18.3(SPI_CLK) U79.17(B3)
ESPI_MISO: J18.7(SPI_MISO) U79.13(B7)
ESPI_MOSI: J18.9(SPI_MOSI) U79.12(B8)
ESPI_SCLK: J18.4(SPI_NSS) U79.16(B4)
EXCITATION: C222.2 R145.2 R152.2 R165.2
EXT_12MHz: R197.1
FAST_SCK: J16.2
FAST_SS: J16.1
FDAT_1V8: U79.7(A6)
I1_CNV: U71.6(CNV)
I1_SCK: U71.8(SCK)
I1_SDI: U71.9(SDI)
I1_SDO: U71.7(SDO)
I2_CNV: U73.6(CNV)
I2_SCK: U73.8(SCK)
I2_SDI: U73.9(SDI)
I2_SDO: U73.7(SDO)
I+: C207.1 R143.1 R150.2 U72.2(-IN_A)
I-: C212.1 R149.2 R154.1 U72.6(-IN_B)
IAM_ALIVE: D9.2(A) U66.15(B5)
IO-15: J3.10
IO_LED_1: R213.1
IO_LED_2: R214.1
IO_LED_3: R215.1
IR_1V8: C197.1 C198.1 C201.1 J11.9 J11.10 J11.11 R135.2 R136.2 R138.2 U67.5(V+) U69.3(VCCA) U69.6(OE)
IR_3V3: J11.14 J11.16
IR_5V0: C200.1 D10.2(ANODE) D11.2(ANODE) J11.1 J11.2 J11.3 J11.4 J12.37 J12.38 J12.39 U68.1(IN)
IR_D0: J11.19 J12.26
IR_D1: J11.36 J12.27
IR_D2: J11.21 J12.24
IR_D3: J11.34 J12.25
IR_D4: J11.23 J12.22
IR_D5: J11.32 J12.23
IR_D6: J11.27 J12.20
IR_D7: J11.30 J12.21
IR_D8: J11.33 J12.18
IR_D9: J11.28 J12.19
IR_D10: J11.31 J12.16
IR_D11: J11.26 J12.17
IR_D12: J11.29 J12.14
IR_D13: J11.24 J12.15
IR_D14: J11.49 R139.2 R141.1
IR_D15: J11.51 R140.1 R142.1
IR_HSYNC: J11.22 J12.13
IR_PCLK: J11.35 J12.11
IR_UART_RX: J11.20 J12.33 R137.1
IR_UART_TX: J11.17 J12.34 R134.1
IR_VSYNC: J11.25 J12.12
KEY_DN: C250.1 D15.2 R204.2 SW3.1
KEY_UP: C251.1 D16.2 R205.2 SW2.1
MCLK: R218.1 U70.41(PR9A/TCK/SCLK)
MCSN: R217.1 U70.48(PR3B/TMS/SCSN) U80.1(CS#)
PGOOD (page PSU1W): R107.2 U63.11(PGOOD)
PWR_EN: R178.1 R209.2 U77.5(EN1) U77.6(EN2)
REF2V5: C1.1 C2.1 C3.1 C4.1 C5.1 C6.1 C7.1 C8.1 C9.1 C10.1 C11.1 C12.1 C13.1 C14.1 C15.1 C16.1 C17.1 C18.1 C19.1 C20.1 C21.1 C22.1 C23.1 C24.1 C25.1 C26.1 C27.1 C28.1 C29.1 C30.1 C31.1 C32.1 C33.1 C34.1 C35.1 C36.1 C37.1 C38.1 C39.1 C40.1 C41.1 C42.1 C43.1 C44.1 C45.1 C46.1 C47.1 C48.1 C49.1 C50.1 C51.1 C52.1 C53.1 C54.1 C55.1 C56.1 C57.1 C58.1 C59.1 C60.1 C61.1 C62.1 C63.1 C64.1 C65.1 C66.1 C67.1 C68.1 C69.1 C70.1 C71.1 C72.1 C73.1 C74.1 C75.1 C76.1 C77.1 C78.1 C79.1 C80.1 C81.1 C82.1 C83.1 C84.1 C85.1 C86.1 C87.1 C88.1 C89.1 C90.1 C91.1 C92.1 C93.1 C94.1 C95.1 C96.1 C117.2 C118.2 U1.6(VDD) U2.1(VDD) U3.3(VDD) U4.1(VDD) U5.3(VDD) U6.6(VDD) U7.6(VDD) U8.1(VDD) U9.3(VDD) U10.3(VDD) U11.1(VDD) U12.6(VDD) U13.6(VDD) U14.1(VDD) U15.3(VDD) U16.3(VDD) U17.1(VDD) U18.6(VDD) U19.6(VDD) U20.1(VDD) U21.3(VDD) U22.3(VDD) U23.1(VDD) U24.6(VDD) U25.6(VDD) U26.1(VDD) U27.3(VDD) U28.3(VDD) U29.1(VDD) U30.6(VDD) U31.6(VDD) U32.1(VDD) U33.3(VDD) U34.3(VDD) U35.1(VDD) U36.6(VDD) U37.6(VDD) U38.1(VDD) U39.3(VDD) U40.3(VDD) U41.1(VDD) U42.6(VDD) U43.6(VDD) U44.3(VDD) U45.1(VDD) U46.3(VDD) U47.1(VDD) U48.6(VDD) U49.6(VREF) U58.1(REF)
REF2V5X: C209.2 C210.2 C218.2 C219.2 Q13.1 R146.2 R153.2 U71.1(REF) U73.1(REF)
SCL3: J3.18 R90.1 U65.5(SCL)
SDA3: J3.20 R93.1 U65.6(SDA)
SPI_CS_1V8: U79.4(A3)
SPI_MISO_1V8: U79.8(A7)
SPI_MOSI_1V8: U79.9(A8)
SPI_SCLK_1V8: U79.5(A4)
SPWM: R163.2
SSPI_CS: R192.2 U78.1(~{CS})
SSPI_SCK: U78.6(SCK)
SSPI_SI: U78.5(SI)
SSPI_SO: U78.2(SO)
SYNC-1: R181.2 R185.1 U77.11(SYNC)
SYNC-2: R170.2 R174.1 U76.11(SYNC)
TCK: J17.1
TDI: J17.3
TDO: J17.5
TMS: J17.2
TXD1_1V8: J3.12 R123.1
TXD_1V8: U79.1(A1)
VBIAS: U72.3(+IN_A) U72.5(+IN_B) U74.6(-IN_B) U74.7(OUT_B)
VCAP_PSU: C188.1 C188.3 R91.1 R92.2
X1: R1.1 U1.3(X1) U2.5(V-) U3.2(V-) U4.5(V-) U5.2(V-) U6.3(X1) U7.3(X1) U8.5(V-) U9.2(V-) U10.2(V-) U11.5(V-) U12.3(X1) U13.3(X1) U14.5(V-) U15.2(V-) U16.2(V-) U17.5(V-) U18.3(X1) U19.3(X1) U20.5(V-) U21.2(V-) U22.2(V-) U23.5(V-) U24.3(X1) U25.3(X1) U26.5(V-) U27.2(V-) U28.2(V-) U29.5(V-) U30.3(X1) U31.3(X1) U32.5(V-) U33.2(V-) U34.2(V-) U35.5(V-) U36.3(X1) U37.3(X1) U38.5(V-) U39.2(V-) U40.2(V-) U41.5(V-) U42.3(X1) U43.3(X1) U44.2(V-) U45.5(V-) U46.2(V-) U47.5(V-) U48.3(X1)
X2: R2.1 U1.1(X2) U2.8(V+) U3.4(V+) U4.8(V+) U5.4(V+) U6.1(X2) U7.1(X2) U8.8(V+) U9.4(V+) U10.4(V+) U11.8(V+) U12.1(X2) U13.1(X2) U14.8(V+) U15.4(V+) U16.4(V+) U17.8(V+) U18.1(X2) U19.1(X2) U20.8(V+) U21.4(V+) U22.4(V+) U23.8(V+) U24.1(X2) U25.1(X2) U26.8(V+) U27.4(V+) U28.4(V+) U29.8(V+) U30.1(X2) U31.1(X2) U32.8(V+) U33.4(V+) U34.4(V+) U35.8(V+) U36.1(X2) U37.1(X2) U38.8(V+) U39.4(V+) U40.4(V+) U41.8(V+) U42.1(X2) U43.1(X2) U44.4(V+) U45.8(V+) U46.4(V+) U47.8(V+) U48.1(X2)
N3267503: D10.1(CATHODE) R133.2
N3267563: D11.1(CATHODE) R132.2
N3267651: Q11.3(COLLECTOR) R132.1
N3267655: Q12.3(COLLECTOR) R133.1
N3267743: Q11.1(BASE) R134.2
N3267747: Q12.1(BASE) R137.2
N3268106: R138.1 R141.2 U67.6(SDA)
N3271476: R135.1 R142.2 U67.1(SCL)
N3495194: C181.1 U63.1(BST1)
N3495202: C181.2 L9.1 U63.16(SW1)
N3495214: C182.1 L9.2 U63.14(SW2)
N3495226: C182.2 U63.13(BST2)
N3495436: C184.2 C185.2 R91.2 R99.1 R107.1 U63.12(VOUT)
N3495602: R98.2 R111.1 U63.4(RUN)
N3495610: C185.1 R99.2 R106.1 U63.7(FB)
N3495638: R96.2 R109.1 U63.10(PWM)
N3495642: R97.2 R110.1 U63.5(MPPC)
N3495714: C192.2 U63.3(VCC)
N3499160: C186.2 C187.1 L10.1 R92.1 R100.2 R101.1 R104.2 U64.4(VIN)
N3499168: L10.2 U64.1(SW)
N3499358: R100.1 R108.2 U64.7(MODE)
N3499470: D8.1(K) D9.1(K) R104.1 R114.2 U64.5(~{SHDN})
N3499478: C189.2 R102.1 R115.2 U64.6(FB)
N3499574: D7.2(ANODE) R105.1
N3503239: C191.2 R95.1 U65.1(IN+)
N3503246: C191.1 R112.1 U65.2(IN-)
N3506922: C196.1 R130.1 R131.1 U66.2(VCCA) U66.10(OE)
N3509536: LD2.1(LD+) R116.2 R117.1 R118.1 R119.1
N3509646: LD2.2(LD-) Q9.3(C)
N3509654: Q8.1(B) R117.2 R121.2 R124.1
N3509658: Q8.3(C) R118.2
N3509670: Q9.1(B) R119.2 R122.1 R125.1
N3509830: Q8.2(E) Q9.2(E) R126.1
N3510191: R127.1 TP15.1(TP)
N3510243: Q10.3(DRAIN) TP16.1(TP)
N3512300: R120.2 R121.1 R122.2 R123.2
N3515615: Q10.1(GATE) R128.1 R129.1
N3521974: R1.2 U51.3(VIN+)
N3522018: R2.2 U51.2(VIN-)
N3522194: R15.2 R16.2 U51.1(RG.1)
N3522206: R15.1 R16.1 U51.8(RG.8)
N3524759: C130.1 U50.5(NR)
N3527418: C105.1 R23.1 R31.2 U55.4(IN-)
N3527435: C105.2 R31.1 R34.1 U55.1(OUT)
N3527532: R23.2 U51.6(VOUT)
N3530743: C106.2 J1.1 R34.2 U58.3(IN+)
N3546634: C128.1 U49.5(NR)
N3652906: C194.2 R129.2
N3673990: J7.1 TP17.1(TP)
N3674102: J7.13 TP23.1(TP)
N3674106: J7.11 TP22.1(TP)
N3674110: J7.9 TP21.1(TP)
N3674114: J7.7 TP20.1(TP)
N3674118: J7.5 TP19.1(TP)
N3674122: J7.3 TP18.1(TP)
N3674280: J7.2 TP30.1(TP)
N3674284: J7.4 TP29.1(TP)
N3674288: J7.6 TP28.1(TP)
N3674292: J7.8 TP27.1(TP)
N3674296: J7.10 TP26.1(TP)
N3674300: J7.12 TP25.1(TP)
N3674304: J7.14 TP24.1(TP)
N3674354: J8.1 TP31.1(TP)
N3674484: J8.2 TP32.1(TP)
N3674488: J8.3 TP33.1(TP)
N3674492: J8.4 TP34.1(TP)
N3674496: J8.5 TP35.1(TP)
N3674500: J8.6 TP36.1(TP)
N3674504: J8.7 TP37.1(TP)
N3674508: J8.8 TP38.1(TP)
N3674998: J9.1 TP39.1(TP)
N3675002: J9.2 TP40.1(TP)
N3675030: J10.1 TP41.1(TP)
N3675046: J9.3 TP42.1(TP)
N3675050: J9.4 TP43.1(TP)
N3675078: J10.2 TP44.1(TP)
N3675094: J9.5 TP45.1(TP)
N3675098: J9.6 TP46.1(TP)
N3675126: J10.3 TP47.1(TP)
N3675142: J9.7 TP48.1(TP)
N3675146: J9.8 TP49.1(TP)
N3675174: J10.4 TP50.1(TP)
N3675190: J9.9 TP51.1(TP)
N3675194: J9.10 TP52.1(TP)
N3675222: J10.5 TP53.1(TP)
N3675238: J9.11 TP54.1(TP)
N3675242: J9.12 TP55.1(TP)
N3675270: J10.6 TP56.1(TP)
N3675274: J9.13 TP57.1(TP)
N3675278: J9.14 TP58.1(TP)
N3675294: J10.7 TP59.1(TP)
N3675298: J10.8 TP60.1(TP)
N3710404: C199.1 C202.1 J13.9 U68.5(OUT) U69.7(VCCB)
N3715489: J13.7 U69.8(B1)
N3715512: J13.8 U69.1(B2)
N3718029: R139.1 U69.5(A1)
N3718139: R140.2 U69.4(A2)
N3739287: C207.2 R143.2 R148.1 U72.1(OUT_A)
N3739307: C211.2 J14.1 R148.2 U71.3(IN+)
N3739635: R144.2 S1.1
N3739639: R145.1 S1.12
N3739717: R147.1 S1.11
N3739789: R149.1 S1.10
N3739845: R150.1 S1.9
N3739913: R151.1 S1.8
N3739941: R152.1 S1.7
N3740053: Q13.2 R153.1 R155.1
N3740065: C212.2 R154.2 R156.1 U72.7(OUT_B)
N3740359: C217.2 J15.1 R156.2 U73.3(IN+)
N3740627: C220.2 R158.2 R159.1 U74.5(+IN_B)
N3740803: R157.2 R158.1
N3741015: C221.2 R160.1 R164.2 U75.3(+IN_A)
N3741157: C221.1 C223.2 R161.1
N3741169: C224.2 R161.2 R162.1
N3741181: C225.2 R162.2 R163.1
N3741227: C222.1 R166.2 U75.1(OUT_A)
N3741311: R166.1 R167.2 U75.2(-IN_A)
N3744017: R168.1 U76.5(EN1) U76.6(EN2)
N3744147: L14.1 U76.9(LX1)
N3744183: R169.1 U76.2(~{RESET1})
N3744231: C233.1 R171.2 R172.1 U76.7(OUT1)
N3744441: C234.2 R173.1 U76.18(PV)
N3744549: L15.1 U76.22(LX2)
N3744577: R175.1 U76.1(~{RESET2})
N3744609: C238.1 R176.2 R177.1 U76.24(OUT2)
N3745119: L16.1 U77.9(LX1)
N3745123: C239.1 C242.2 L16.2 R179.2 R183.2
N3745159: R180.1 U77.2(~{RESET1})
N3745207: C242.1 R182.2 R183.1 U77.7(OUT1)
N3745417: C243.2 R184.1 U77.18(PV)
N3745541: L17.1 U77.22(LX2)
N3745545: C244.1 C247.2 L17.2 R186.2 R189.2
N3745573: R187.1 U77.1(~{RESET2})
N3745605: C247.1 R188.2 R189.1 U77.24(OUT2)
N3746963: R190.2 R193.1 U78.7(~{HOLD})
N3746967: R191.2 R194.1 U78.3(~{WP})
N3747790: R195.1 R196.1 Y2.1(EN)
N3747850: R197.2 Y2.3(OUT)
N3751883: C253.1 C255.2 R206.1 R207.1 U79.19(VCCB)
N3752349: J18.1(VCC5V2) R208.1
N3752483: J18.10(GPIO) R209.1
N3790102: D17.1(CATHODE) R212.2
N3790142: D19.1(CATHODE) R211.2
N3790170: D18.1(CATHODE) R210.2
N3790226: Q14.3(COLLECTOR) R210.1
N3790230: Q15.3(COLLECTOR) R211.1
N3790234: Q16.3(COLLECTOR) R212.1
N3790314: Q14.1(BASE) R213.2
N3790318: Q15.1(BASE) R214.2
N3790322: Q16.1(BASE) R215.2
N3796363: R216.1 R218.2 U80.6(SCLK)
N3796473: U70.46(PR5A/TDI/SSI) U80.2(SO/SIO1)
N3796477: R219.1 U80.7(RST#/SIO3)
N3796517: R220.1 U80.3(W#/SIO2)
N3796547: U70.45(PR5B/TDO/SSO) U80.5(SI/SIO0)

Not connected (* = marked no-connect by the designer): J3 1* 2* 3* 4* 5* 6* 7* 8* 9* 11* 13* 14* 15* 38*; J4 2*; J5 2*; J8 9* 10*; J10 9* 10*; J11 39* 40* 41* 42* 43* 45* 46* 48* 52* 54* 55* 58* 59* 60* 61* 62* 63* 64* 65* 66* 68* 69*; J12 2* 3* 5* 6* 8* 9* 29* 30* 31* 32*; J13 1* 2* 3* 4* 5* 6*; J16 6*; LD2 3(PD-)* 4(PD+)*; S1 2* 3* 4* 5* 6*; U1 2(NC.2)* 5(NC.5)*; U2 2(NC.2)* 3(NC.3)* 6(NC.6)* 7(NC.7)*; U4 2(NC.2)* 3(NC.3)* 6(NC.6)* 7(NC.7)*; U6 2(NC.2)* 5(NC.5)*; U7 2(NC.2)* 5(NC.5)*; U8 2(NC.2)* 3(NC.3)* 6(NC.6)* 7(NC.7)*; U11 2(NC.2)* 3(NC.3)* 6(NC.6)* 7(NC.7)*; U12 2(NC.2)* 5(NC.5)*; U13 2(NC.2)* 5(NC.5)*; U14 2(NC.2)* 3(NC.3)* 6(NC.6)* 7(NC.7)*; U17 2(NC.2)* 3(NC.3)* 6(NC.6)* 7(NC.7)*; U18 2(NC.2)* 5(NC.5)*; U19 2(NC.2)* 5(NC.5)*; U20 2(NC.2)* 3(NC.3)* 6(NC.6)* 7(NC.7)*; U23 2(NC.2)* 3(NC.3)* 6(NC.6)* 7(NC.7)*; U24 2(NC.2)* 5(NC.5)*; U25 2(NC.2)* 5(NC.5)*; U26 2(NC.2)* 3(NC.3)* 6(NC.6)* 7(NC.7)*; U29 2(NC.2)* 3(NC.3)* 6(NC.6)* 7(NC.7)*; U30 2(NC.2)* 5(NC.5)*; U31 2(NC.2)* 5(NC.5)*; U32 2(NC.2)* 3(NC.3)* 6(NC.6)* 7(NC.7)*; U35 2(NC.2)* 3(NC.3)* 6(NC.6)* 7(NC.7)*; U36 2(NC.2)* 5(NC.5)*; U37 2(NC.2)* 5(NC.5)*; U38 2(NC.2)* 3(NC.3)* 6(NC.6)* 7(NC.7)*; U41 2(NC.2)* 3(NC.3)* 6(NC.6)* 7(NC.7)*; U42 2(NC.2)* 5(NC.5)*; U43 2(NC.2)* 5(NC.5)*; U45 2(NC.2)* 3(NC.3)* 6(NC.6)* 7(NC.7)*; U47 2(NC.2)* 3(NC.3)* 6(NC.6)* 7(NC.7)*; U48 2(NC.2)* 5(NC.5)*; U60 4(NC)*; U63 8(NC.8)* 9(NC.9)*; U68 4(NC)*; U70 1(DPHY0_DP2) 2(DPHY0_DN2) 3(DPHY0_DN0) 4(DPHY0_DP0) 8(PB30B/PCLKC5_3/VREF5_2) 9(PB30A/PCLKT5_3) 10(PB20B/PCLKC5_1/LLC_GPLL0C_IN/ADC_CN3) 11(PB20A/PCLKT5_1/LLC_GPLL0T_IN/ADC_CP3) 13(PB16B/CDR_RXN0/ADC_CN0/COMP1N) 14(PB16A/CDR_RXP0/VREF5_1/ADC_CP0/COMP1P) 15(PB18B/PCLKC5_0/CDR_RXN1/ADC_CN1/COMP2N) 16(PB18A/PCLKT5_0/CDR_RXP1/ADC_CP1/COMP2P) 19(PB26A/PCLKT5_2/ADC_CP2/COMP3P) 20(PB26B/PCLKC5_2/ADC_CN2/COMP3N) 22(PB56A/PCLKT3_0/VREF3_1/ADC_CP5) 23(PB56B/PCLKC3_0/ADC_CN5) 24(PB60A/PCLKT3_1/ADC_CP6) 25(PB60B/PCLKC3_1/ADC_CN6) 27(PB64A/ADC_CP8) 28(PB64B/ADC_CN8) 30(PB66A/PCLKT3_2/ADC_CP13) 31(PB66B/PCLKC3_2/ADC_CN13) 33(PB68A/PCLKT3_3/ADC_CP14) 34(PB68B/PCLKC3_3/ADC_CN14) 36(PB70A/LRC_GPLL0T_IN) 37(PB70B/LRC_GPLL0C_IN/VREF3_2) 42(PR7A/SDA) 43(PR9B) 44(PR7B/SCL) 50(JTAG_EN) 51(PT63A/MISO/MD1) 52(PT65A/MD3) 53(PT65B/MCSNO/MSDO) 55(PT63B/MD2) 56(PT61A/MCSN/PCLKT0_1) 57(PT61B/MOSI/MD0) 58(PT59B/DONE) 59(PT59A/MCLK/PCLKT0_0) 60(PT57B/PROGRAMN) 61(PT57A/INITN) 64(DPHY0_DP3) 65(DPHY0_DN3) 66(DPHY0_DP1) 67(DPHY0_DN1) 68(DPHY0_CKP) 69(DPHY0_CKN)

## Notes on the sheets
sheet 1
- ATTENTION !!!
  PCLK MUST BE ROUTED TO FPGA CLK IN PIN
  FOR USING AS A CLOCK SIGNAL
- Yantai InfiRay Lite640x512 Infrared Image Sensor
- Yantai InfiRay MicroIII 256L Infrared Image Sensor
  256*192@14bits
  CDS2 Interface 1.8V IO:  PCLK, VSYNC, HSYNC, DATA[0:13] (Pixel + Temperature)
  350mW
- CDS3 1.8V IO
- ATTENTION !!!
  PCLK MUST BE ROUTED TO FPGA CLK IN PIN
  FOR USING AS A CLOCK SIGNAL
- 1.8V IO
- E15
- F9
- E12
- G10
- E13
- M14
- IR_PCLK
- IR_HSYNC
- G9
- E9
- F15
- E13
- IR_VSYNC
- IR_D13
- J11
- G9
- H15
- F15
- IR_D12
- IR_D11
- K11
- K7
- J15
- H15
- IR_D10
- IR_D9
- M15
- J11
- K11
- K12
- L12
- J15
- K12
- IR_D6
- IR_D8
- IR_D5
- IR_D7
- E9
- K7
- M15
- M16
- L12
- IR_D4
- IR_D3
- G10
- M14
- N16
- M16
- IR_D2
- IR_D1
- F9
- N16
- IR_D0
- E12
- E15
- Crossed-Wire
  for UART
- T10
- T11
- 3.3V IO
  VCCA<=VCCB
- P_485_B
  P_485_A
  GPIO0
  GPIO14
  GPIO19
  GPIO20
  U0RXD
  U0TXD
  VCC_3V3
  GND
- TEMPERATURE
  SENSOR
- ADDR: 1001000x
sheet 2
- AD8602 CMOS, Rail-to-Rail I/O OPA
  Single power supply : 2.7V to 5.5V
  Low supply current : 1mA
  Low input bias current : 100pA
  High output current : +/-30mA
  GBP: 8.2MHz
  Slew rate: 5.2V/us
- VDD=2.5V
- PIO=1.8V
- 2.5V
- 1.25V
- 0V
- 5V-> (1V2, 1V8)  -> ( 2V5, 3V3)
- Freq:38KHz
  Amplitude: 7Vpp
- POWER UP SEQUENCE
- 5V -> 3V3
- TL431
  PRECISION +/-1%
- 1mA < (Vcc-Vout)/R < 500mA
  (3.3-2.5)/4mA=200R
- 5V -> 2V5
- Cout_nom=27.5uS*3A/2.8V=29.5uF
- Anti-Aliasing Filter
- VDD=2.5V
- PIO=1.8V
- LPF
  fcutoff=1/(2*pi*R*C)=312KHz
- Adjustable Output Voltage Equation
  R1=R2*(Vout/Vfb-1)
  R2<=100K, Vfb=800mV
  R2=48K, R1=102K @Vout=2.5V
- Frequency Compensation
  C1=50*R2/R1(pF)
  =50*(48K/102K)
  =23.53pF
- SPI PROGRAMMING
  INTERFACE
- SOFT JTAG FOR REVEAL
- Adjustable Output Voltage Equation
  R1=R2*(Vout/Vfb-1)
  R2<=100K, Vfb=800mV
  R2=49.9K, R1=154K @Vout=3.3V
- Frequency Compensation
  C1=50*R2/R1(pF)
  =50*(48K/120K)
  =16pF
- Unity-Gain Buffer
- VBIAS=(680R+28K)/(680R+28K+47K)*3.3V=1.25V
- 5V -> 1V8
  5V -> 1V2
- 1.8V
- 5.0V
- OUTPUT BUFFER
- 0.9V
- Adjustable Output Voltage Equation
  R1=R2*(Vout/Vfb-1)
  R2<=100K, Vfb=800mV
  R2=100K, R1=49.9K @Vout=1.2V
- 2.5V
- 0V
- 10*Fsw=380KHz
- 0V
- Frequency Compensation
  C1=50*R2/R1(pF)
  =50*(100K/49.9K)
  =100pF
- 38KHz
- Adjustable Output Voltage Equation
  R1=R2*(Vout/Vfb-1)
  R2<=100K, Vfb=800mV
  R2=100K, R1=125K @Vout=1.8V
- LOW PASS FILTER
- Frequency Compensation
  C1=50*R2/R1(pF)
  =50*(100K/125K)
  =40pF
- Vout=Vin*(1+Rf/R)
- 5V/1.8V=2.78
- f=1/(2*pi*R*C)=53KHz
- External Oscillator
  12MHz->PLL->48MHz
- Cout_nom=27.5uS*3A/1.8V=45.8uF
- IO LEVEL
  1V8 OR 3V3
- ONSEMI
  EEPROM Serial
  512Kbits SPI
- FOR DEBUG
  ONLY
- JTAG2SPI
  MASTER_SPI_BRIDGE
sheet 3
- 2.54MM HEADER
  HW-USBN-2B
- FPC CONNECTOR
  LATTICE FPGA
sheet 4
- CHARGING
- STEP-UP CONVERTER
- VIN: 5V~7V
- LTC3539
  2A 1MHz Synchronous Step-Up DC/DC Converters
  VIN=0.7V~5V
- L=Vout*(1-D)*T/(CR*Iout)
  =5.0*(1-50%)*1uS/(30%*200mA)
  =4.2uH
- MODE = High: Burst Mode operation at light loads, >=0.88V
  MODE = Low: Fixed frequency PWM Mode, <0.3V
- Vout=1.175*(1+R1/R2)
  Vout=1.175*(1+470K/143K)=5.0V
- P5V0
- H/C Type
  Compatible
  2F/5.5V
- 5V/15mA=333R
- Vout=1.2V*(1+R2/R1)
  =1.2V*(1+1M/309K)
  =5.08V
- RUN:
  pull this pin above 1.1V to enable VCC regulator
  and above 1.28V to enable the converter.
- LED turns on at
  I=(5.0-2.2)/56K=50uA
- A0=0, I2C SLAVE ADDRESS=1000000
- PWM
  1: Automatic burst mode.
  0: Fixed PWM mode.
- VFD=0.3V @1mA
- RUN 432/(1000+432)*5=1.5V
- Rshunt=81.92mV/500mA=164mR
  Pshunt=81.92mV*500mA=40.96mW
- SHDN_N: LOW<0.3V, HIGH>0.88V
- Vin(MPPC)=1.175*(1+R5/R6)
  =1.175*(1+470K/110K)
  =6.2V
- 850nm Photovoltaic Cell outputs maximum power at 6.2V
- VCAP will be charged to 5V.
  In order to keep AUTO_EN available during FPGA starts,
  choose 4V as the lowest value,
  VCAP drops from 5V to 4V, FPGA starts up and outputs IAM_ALIVE to lock SHDN.
- VCAP=5.0V, AUTO_EN=4.3K/(10K+4.3K)*VCAP=1.5V, SHDN=AUTO_EN-VFD=1.5-0.3=1.2V
  VCAP=4.0V, AUTO_EN=4.3K/(10K+4.3K)*VCAP=1.2V, SHDN=AUTO_EN-VFD=1.2-0.3=0.9V
- Vfd=1.23V
- IAM_ALIVE=1.8V, SHDN=IAM_ALIVE-VFD=1.8-0.3=1.5V
- R1
- R3
- Rin
- Ve
- RESERVED IO
- R2
- R4
- Re
- VCCA<=VCCB
sheet 6
- TMR SENSOR X16 CONNECTED IN PARALLEL
- VDD=2.5V
- PIO=1.8V
